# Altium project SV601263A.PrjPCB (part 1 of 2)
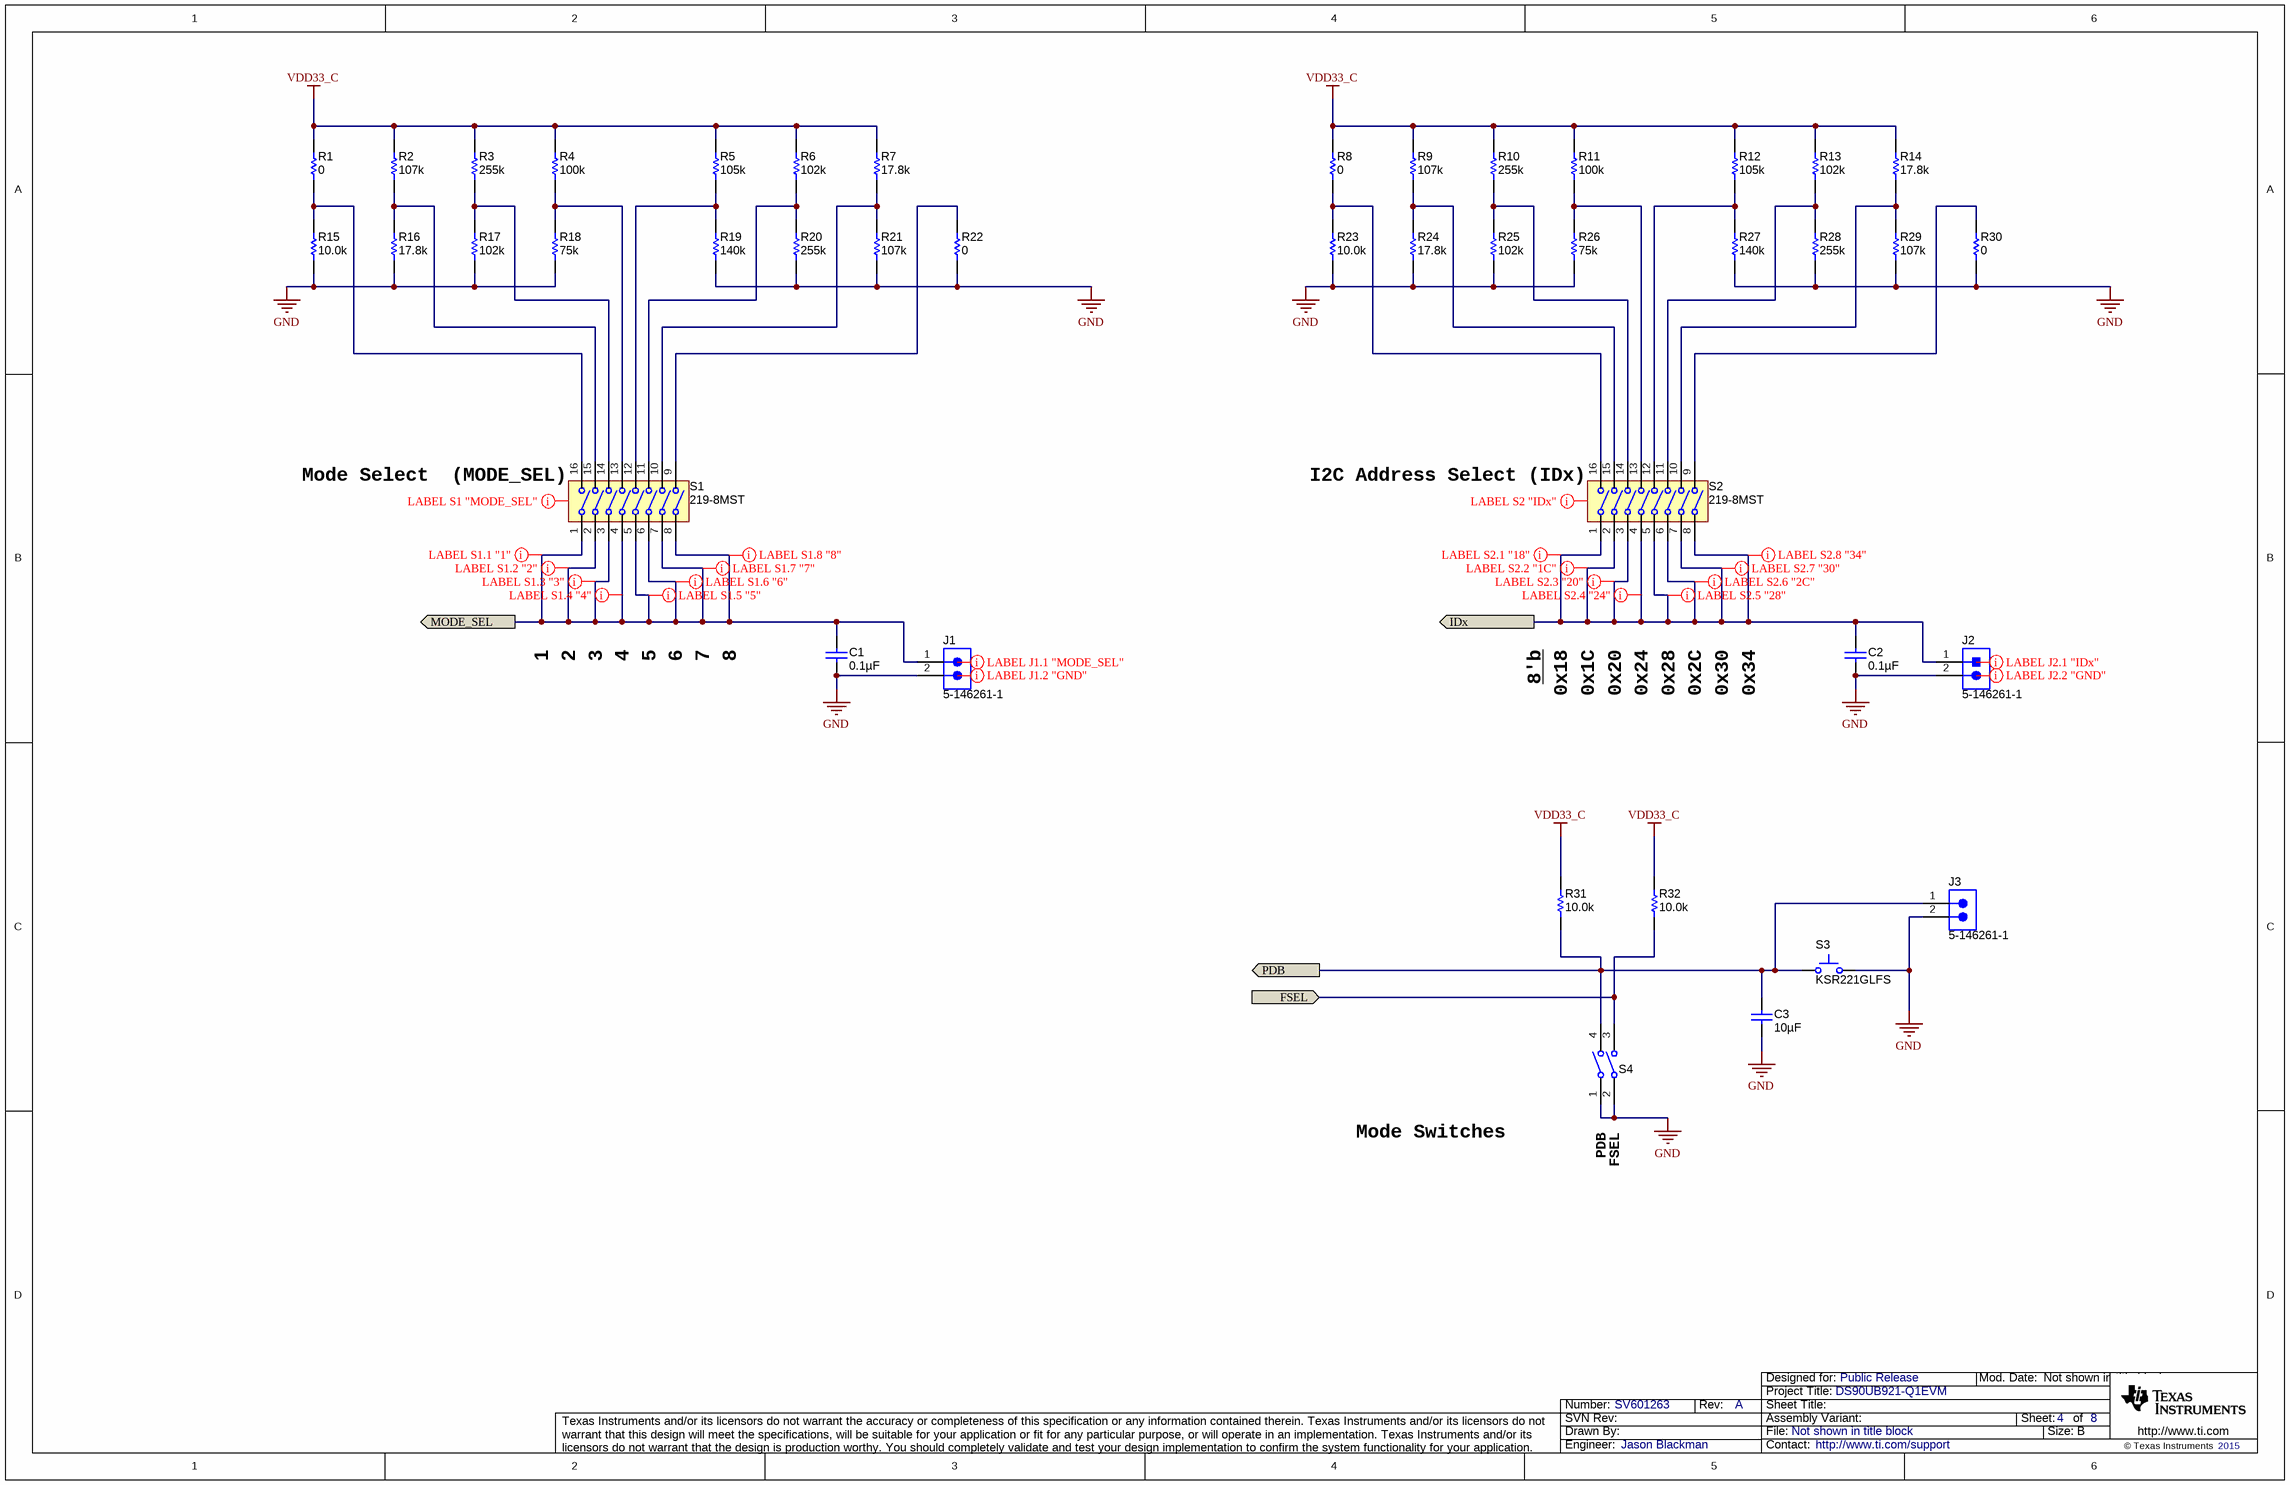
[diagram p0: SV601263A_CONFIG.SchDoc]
CopyrightYear: 2015; PCB_Layout: A; PCB_Rev: A; PRJ_Customer: Public Release; PRJ_Engineer: Jason Blackman; PRJ_Number: SV601263; PRJ_Title: DS90UB921-Q1EVM; SCH_Rev: A; TechSupport: http://www.ti.com/support
7 sheets, 306 parts. Net scope: flat (ports and power ports of the same name join across sheets).
Board file: SV601263A.PcbDoc
Sheets:
  SV601263A_CONFIG.SchDoc
  SV601263A_CONNECTORS.SchDoc
  SV601263A_Cover Sheet_Block.SchDoc
  SV601263A_DS90UB921.SchDoc
  SV601263A_LED.SchDoc
  SV601263A_MSP430F5529.SchDoc
  SV601263A_Power.SchDoc

## Sheet SV601263A_CONFIG.SchDoc
size 431 x 279 mm; Date: Not shown in title block; ApprovedBy: Not shown in title block; CheckedBy: Not shown in title block; Author: Not shown in title block; CompanyName: Not shown in title block; Engineer: Not shown in title block; Organization: Not shown in title block; Address1: Not shown in title block; Address2: Not shown in title block; Address3: Not shown in title block; Address4: Not shown in title block; DocumentNumber: 6; Revision: Use project parameter SCH_Rev; SheetNumber: 4; SheetTotal: 8

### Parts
C1  ValueDisplayed: 0.1µF  [0402]  (hidden comment: GRM155R71C104KA88D)
C2  ValueDisplayed: 0.1µF  [0402]  (hidden comment: GRM155R71C104KA88D)
C3  ValueDisplayed: 10µF  [0805_HV]  (hidden comment: GRM21BR71A106KE51L)
J1  5-146261-1  [CONN_5-146261-1]
J2  5-146261-1  [CONN_5-146261-1]
J3  5-146261-1  [CONN_5-146261-1]
R1  value 0  [0402]  (hidden comment: ERJ-2GE0R00X)
R2  value 107k  [0402]  (hidden comment: CRCW0402107KFKED)
R3  value 255k  [0402]  (hidden comment: CRCW0402255KFKED)
R4  value 100k  [0402]  (hidden comment: ERJ-2RKF1003X)
R5  value 105k  [0402]  (hidden comment: CRCW0402105KFKED)
R6  value 102k  [0402]  (hidden comment: CRCW0402102KFKED)
R7  value 17.8k  [0402]  (hidden comment: CRCW040217K8FKED)
R8  value 0  [0402]  (hidden comment: ERJ-2GE0R00X)
R9  value 107k  [0402]  (hidden comment: CRCW0402107KFKED)
R10  value 255k  [0402]  (hidden comment: CRCW0402255KFKED)
R11  value 100k  [0402]  (hidden comment: ERJ-2RKF1003X)
R12  value 105k  [0402]  (hidden comment: CRCW0402105KFKED)
R13  value 102k  [0402]  (hidden comment: CRCW0402102KFKED)
R14  value 17.8k  [0402]  (hidden comment: CRCW040217K8FKED)
R15  ValueDisplayed: 10.0k  [0402]  (hidden comment: CRCW040210K0FKED)
R16  value 17.8k  [0402]  (hidden comment: CRCW040217K8FKED)
R17  value 102k  [0402]  (hidden comment: CRCW0402102KFKED)
R18  value 75k  [0402]  (hidden comment: CRCW040275K0JNED)
R19  value 140k  [0402]  (hidden comment: CRCW0402140KFKED)
R20  value 255k  [0402]  (hidden comment: CRCW0402255KFKED)
R21  value 107k  [0402]  (hidden comment: CRCW0402107KFKED)
R22  value 0  [0402]  (hidden comment: ERJ-2GE0R00X)
R23  ValueDisplayed: 10.0k  [0402]  (hidden comment: CRCW040210K0FKED)
R24  value 17.8k  [0402]  (hidden comment: CRCW040217K8FKED)
R25  value 102k  [0402]  (hidden comment: CRCW0402102KFKED)
R26  value 75k  [0402]  (hidden comment: CRCW040275K0JNED)
R27  value 140k  [0402]  (hidden comment: CRCW0402140KFKED)
R28  value 255k  [0402]  (hidden comment: CRCW0402255KFKED)
R29  value 107k  [0402]  (hidden comment: CRCW0402107KFKED)
R30  value 0  [0402]  (hidden comment: ERJ-2GE0R00X)
R31  ValueDisplayed: 10.0k  [0402]  (hidden comment: CRCW040210K0FKED)
R32  ValueDisplayed: 10.0k  [0402]  (hidden comment: CRCW040210K0FKED)
S1  219-8MST  [SW_219-8MST]
S2  219-8MST  [SW_219-8MST]
S3  KSR221GLFS  [KSR]
S4  218-2LPST  [SW_218-2LP]  (value not drawn)

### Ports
FSEL, IDx, MODE_SEL, PDB

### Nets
GND: C1.2 C2.2 C3.2 J1.2 J2.2 J3.2 R15.1 R16.1 R17.1 R18.1 R19.1 R20.1 R21.1 R22.1 R23.1 R24.1 R25.1 R26.1 R27.1 R28.1 R29.1 R30.1 S3.2 S4.1 S4.2
VDD33_C: R1.2 R2.2 R3.2 R4.2 R5.2 R6.2 R7.2 R8.2 R9.2 R10.2 R11.2 R12.2 R13.2 R14.2 R31.2 R32.2
FSEL: R32.1 S4.3 ; port FSEL
IDx: C2.1 J2.1 S2.1 S2.2 S2.3 S2.4 S2.5 S2.6 S2.7 S2.8 ; port IDx
MODE_SEL: C1.1 J1.1 S1.1 S1.2 S1.3 S1.4 S1.5 S1.6 S1.7 S1.8 ; port MODE_SEL
NetC3_1: C3.1 J3.1 R31.1 S3.1 S4.4 ; port PDB
NetR1_1: R1.1 R15.2 S1.16(1A)
NetR2_1: R2.1 R16.2 S1.15(2A)
NetR3_1: R3.1 R17.2 S1.14(3A)
NetR4_1: R4.1 R18.2 S1.13(4A)
NetR5_1: R5.1 R19.2 S1.12(5A)
NetR6_1: R6.1 R20.2 S1.11(6A)
NetR7_1: R7.1 R21.2 S1.10(7A)
NetR8_1: R8.1 R23.2 S2.16(1A)
NetR9_1: R9.1 R24.2 S2.15(2A)
NetR10_1: R10.1 R25.2 S2.14(3A)
NetR11_1: R11.1 R26.2 S2.13(4A)
NetR12_1: R12.1 R27.2 S2.12(5A)
NetR13_1: R13.1 R28.2 S2.11(6A)
NetR14_1: R14.1 R29.2 S2.10(7A)
NetR22_2: R22.2 S1.9(8A)
NetR30_2: R30.2 S2.9(8A)

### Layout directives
mark named LABEL S2 "IDx": (no net found under the mark)
rule Undefined: (no net found under the mark), IDx, MODE_SEL
mark named LABEL S1 "MODE_SEL": (no net found under the mark)

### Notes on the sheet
- (near S1) Mode Select  (MODE_SEL)
- (near S2) I2C Address Select (IDx)
- 1
- 2
- 3
- 4
- 5
- 6
- 7
- 8
- 8'b
- 0x18
- 0x1C
- 0x20
- 0x24
- 0x28
- 0x2C
- 0x30
- 0x34
- Mode Switches
- PDB
- FSEL

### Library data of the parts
C1 C2 = GRM155R71C104KA88D: CAP, CERM, 0.1uF, 16V, +/-10%, X7R, 0402; Manufacturer: MuRata; Polarized: N; CompType: Capacitor; U/M: EA; Cap_F: 0.0000001; Tolerance_%: 10; Value1: Unknown; VDC_V: 16; TaMin_C: -55; TaMax_C: 125
C3 = GRM21BR71A106KE51L: CAP, CERM, 10uF, 10V, +/-10%, X7R, 0805; Manufacturer: MuRata; Polarized: N; CompType: Capacitor; U/M: EA; Cap_F: 0.00001; Tolerance_%: 10; ESR_Ohm: 0.003; Value1: 0.003 ohm; TaMin_C: -55; TaMax_C: 125; Cap_Case: 0805
J1-J3 = 5-146261-1: Header, 100mil, 2x1, Gold, TH; Manufacturer: TE Connectivity; SymbolCreator: a0412235; U/M: EA
R1 R8 R22 R30 = ERJ-2GE0R00X: RES, 0 ohm, 5%, 0.063W, 0402; Manufacturer: Panasonic; CompType: Resistor; Value_Code: 0000; Tolerance_%: 5; Power_W: 0.063; VDC_V: 50; TempCo: 600 ppm/C; EIA_Code: E24; U/M: EA
R2 R9 R21 R29 = CRCW0402107KFKED: RES, 107k ohm, 1%, 0.063W, 0402; Manufacturer: Vishay-Dale; CompType: Resistor; Res_ohm: 107000; Tolerance_%: 1; Power_W: 0.063; VDC_V: 50; TempCo: 100 ppm/C; EIA_Code: E96; U/M: EA
R3 R10 R20 R28 = CRCW0402255KFKED: RES, 255k ohm, 1%, 0.063W, 0402; Manufacturer: Vishay-Dale; CompType: Resistor; Res_ohm: 255000; Tolerance_%: 1; Power_W: 0.063; VDC_V: 50; TempCo: 100 ppm/C; EIA_Code: E96; U/M: EA
R4 R11 = ERJ-2RKF1003X: RES, 100k ohm, 1%, 0.1W, 0402; Manufacturer: Panasonic; CompType: Resistor; Res_ohm: 100000; Tolerance_%: 1; Power_W: 0.1; VDC_V: 50; TempCo: 100 ppm/C; EIA_Code: E96; U/M: EA
R5 R12 = CRCW0402105KFKED: RES, 105k ohm, 1%, 0.063W, 0402; Manufacturer: Vishay-Dale; CompType: Resistor; Res_ohm: 105000; Tolerance_%: 1; Power_W: 0.063; VDC_V: 50; TempCo: 100 ppm/C; EIA_Code: E96; U/M: EA
R6 R13 R17 R25 = CRCW0402102KFKED: RES, 102k ohm, 1%, 0.063W, 0402; Manufacturer: Vishay-Dale; CompType: Resistor; Res_ohm: 102000; Tolerance_%: 1; Power_W: 0.063; VDC_V: 50; TempCo: 100 ppm/C; EIA_Code: E96; U/M: EA
R7 R14 R16 R24 = CRCW040217K8FKED: RES, 17.8k ohm, 1%, 0.063W, 0402; Manufacturer: Vishay-Dale; CompType: Resistor; Res_ohm: 17800; Value_Code: 17k8; Tolerance_%: 1; Power_W: 0.063; VDC_V: 50; TempCo: 100 ppm/C; EIA_Code: E96; U/M: EA
R15 R23 R31 R32 = CRCW040210K0FKED: RES, 10.0 k, 1%, 0.063 W, 0402; Manufacturer: Vishay-Dale; CompType: Resistor; Value: 10.0k; Res_ohm: 10000; Value_Code: 10k0; Tolerance_%: 1; Power_W: 0.063; Value2: 0.063W; VDC_V: 50; TempCo: 100 ppm/C; EIA_Code: E96; U/M: EA
R18 R26 = CRCW040275K0JNED: RES, 75k ohm, 5%, 0.063W, 0402; Manufacturer: Vishay-Dale; CompType: Resistor; Res_ohm: 75000; Value_Code: 75k0; Tolerance_%: 5; Power_W: 0.063; VDC_V: 50; TempCo: 200 ppm/C; EIA_Code: E24; U/M: EA
R19 R27 = CRCW0402140KFKED: RES, 140k ohm, 1%, 0.063W, 0402; Manufacturer: Vishay-Dale; CompType: Resistor; Res_ohm: 140000; Tolerance_%: 1; Power_W: 0.063; VDC_V: 50; TempCo: 100 ppm/C; EIA_Code: E96; U/M: EA
S1 S2 = 219-8MST: Switch, Slide, SPST 8 poles, SMT; Manufacturer: CTS Electrocomponents; SymbolCreator: a0412235; VDC_V: 20; SwitchFunction: Off-On; PositionCount: 8; CurrentRating_mA: 100
S3 = KSR221GLFS: Switch, Normally open, 2.3N force, 200k operations, SMD; Manufacturer: C and K Components; Circuit: SPST Switch; VDC_V: 32; SwitchFunction: Off-Mom; PositionCount: 1; CurrentRating_mA: 1001
S4 = 218-2LPST: Switch, SPST, 2 Pos, 25mA, 24VDC, SMD; Manufacturer: CTS Electrocomponents; SymbolCreator: Altium; VDC_V: 24; SwitchFunction: Off-On; PositionCount: 2; CurrentRating_mA: 25

## Sheet SV601263A_CONNECTORS.SchDoc
size 431 x 279 mm; Date: Not shown in title block; ApprovedBy: Not shown in title block; CheckedBy: Not shown in title block; Author: Not shown in title block; CompanyName: Not shown in title block; Engineer: Not shown in title block; Organization: Not shown in title block; Address1: Not shown in title block; Address2: Not shown in title block; Address3: Not shown in title block; Address4: Not shown in title block; DocumentNumber: 7; Revision: Use project parameter SCH_Rev; SheetNumber: 5; SheetTotal: 8
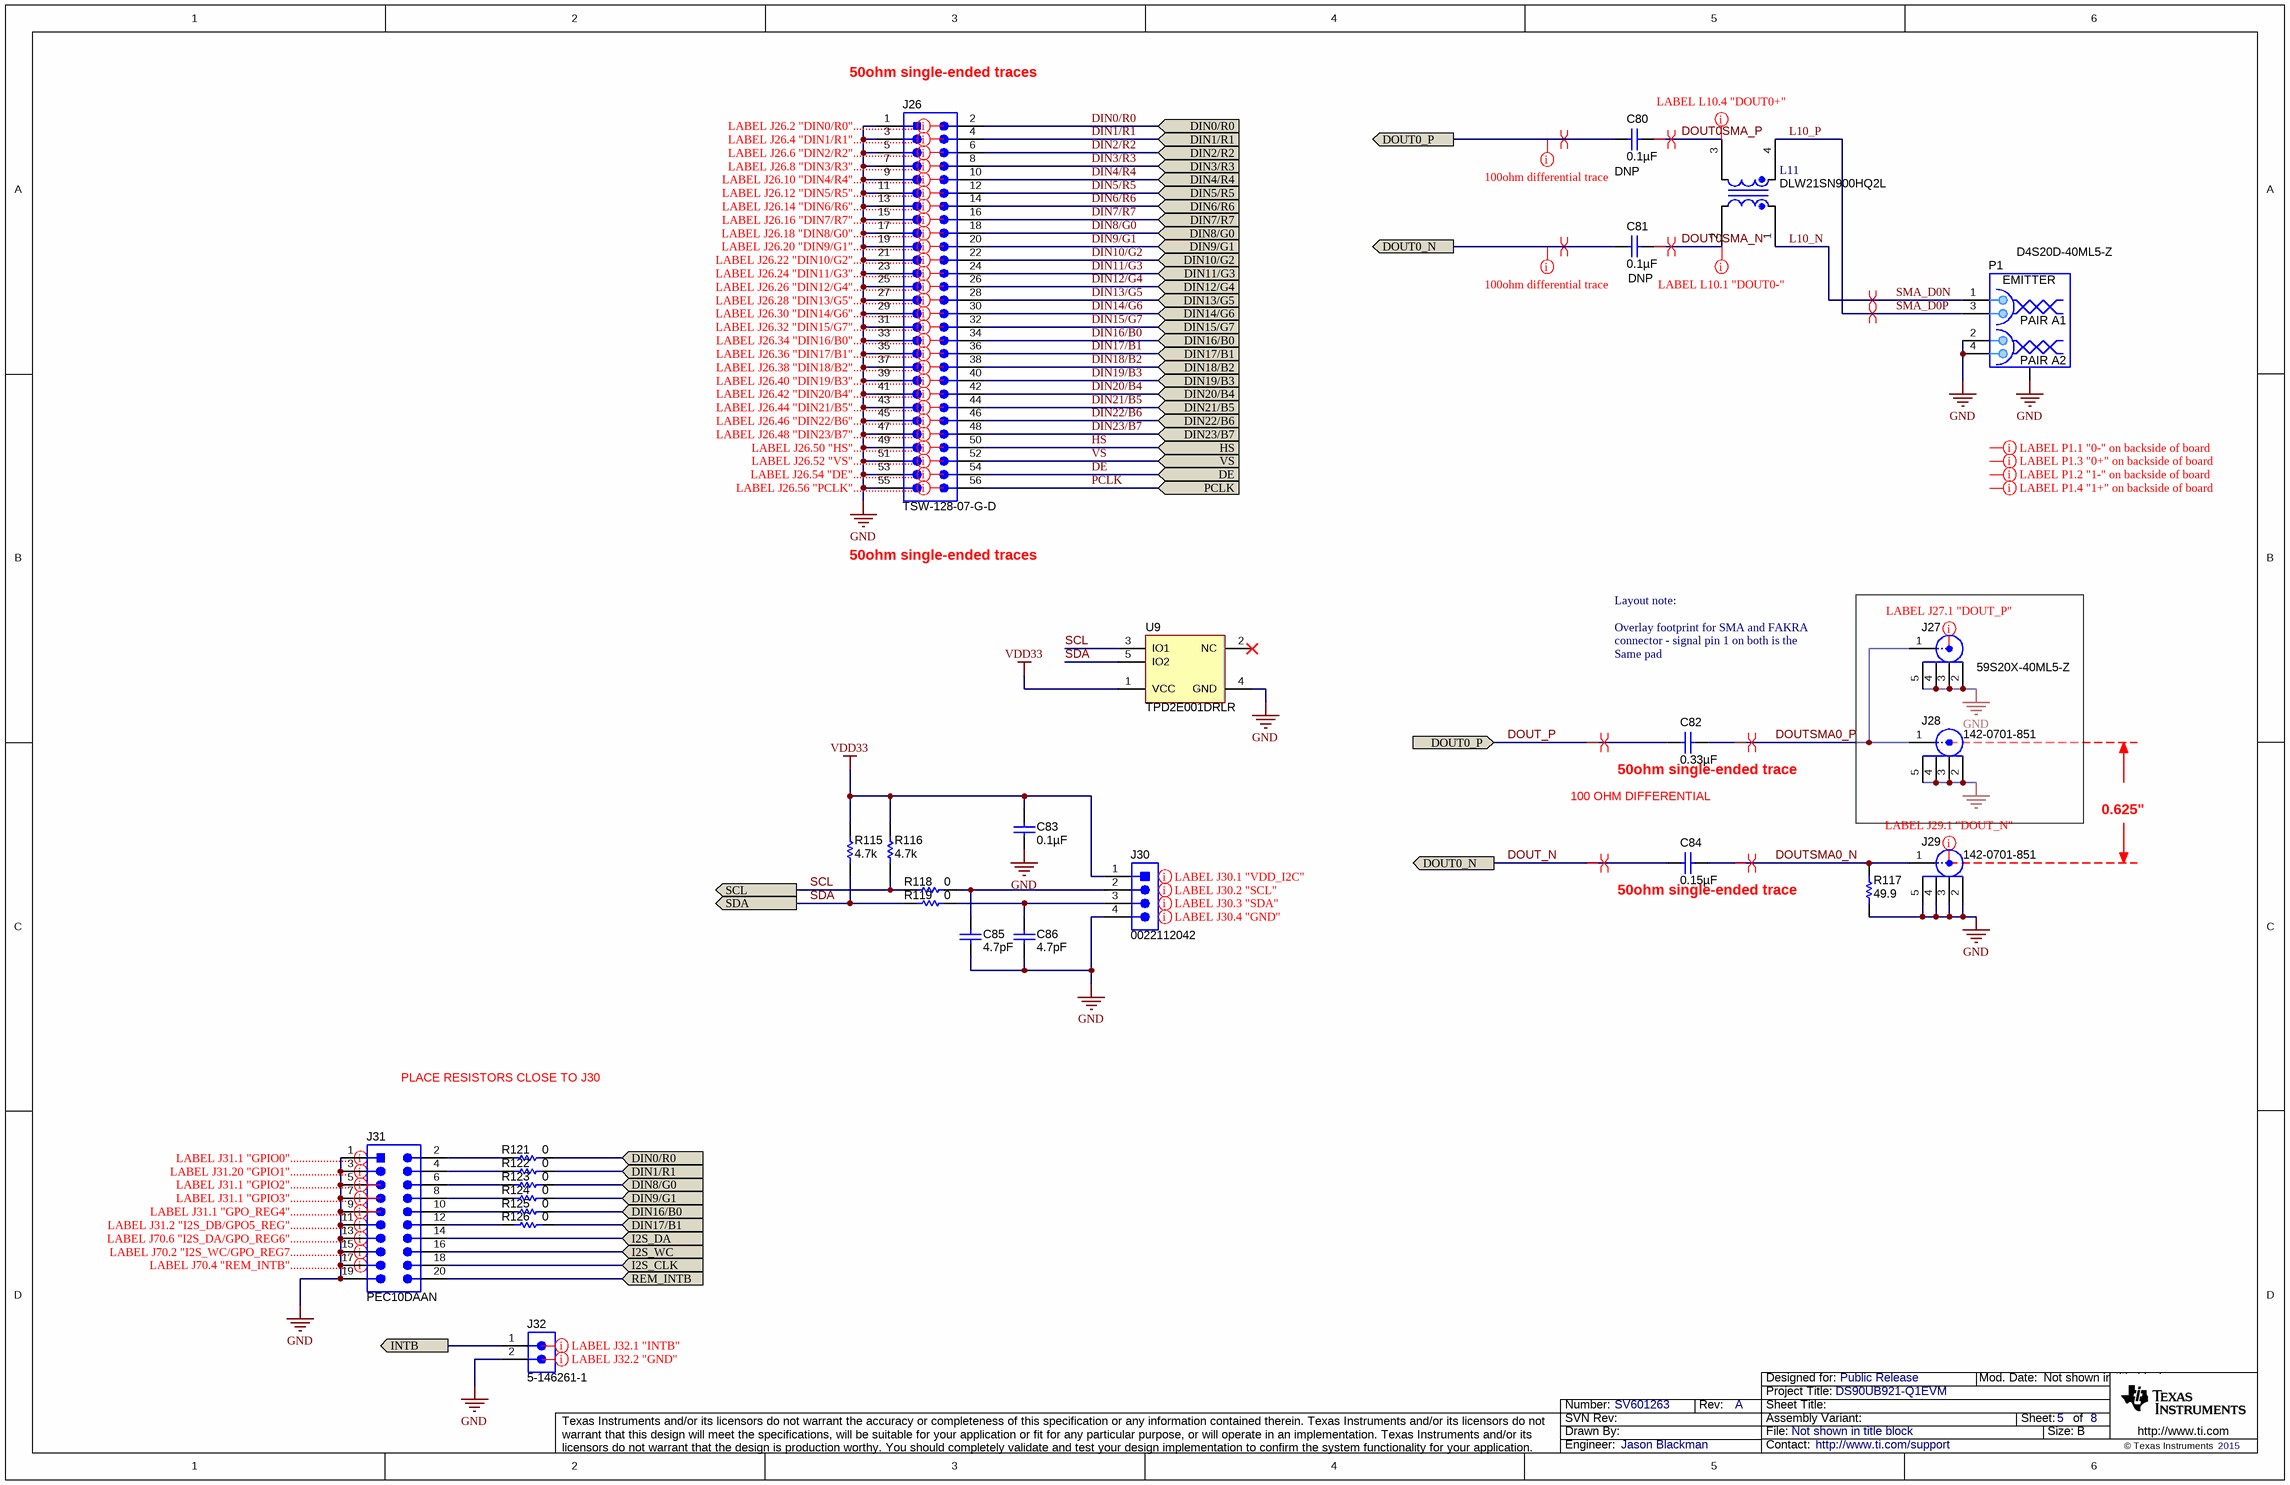
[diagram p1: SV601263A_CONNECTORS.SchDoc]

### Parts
C80  DNP  ValueDisplayed: 0.1µF  [0402]
C81  DNP  ValueDisplayed: 0.1µF  [0402]
C82  ValueDisplayed: 0.33µF  [0402]  (hidden comment: C1005X5R1A334K050BB)
C83  ValueDisplayed: 0.1µF  [0402]  (hidden comment: GRM155R71C104KA88D)
C84  ValueDisplayed: 0.15µF  [0402]  (hidden comment: C1005X5R1A154K050BC)
C85  ValueDisplayed: 4.7pF  [0402]  (hidden comment: GRM1555C1E4R7CA01D)
C86  ValueDisplayed: 4.7pF  [0402]  (hidden comment: GRM1555C1E4R7CA01D)
J26  TSW-128-07-G-D  [Samtec_TSW-128-07-G-D]
J27  59S20X-40ML5-Z  [Rosenberger_59S20X-40ML5-Z]
J28  142-0701-851  [Emerson_142-0701-851]
J29  142-0701-851  [Emerson_142-0701-851]
J30  0022112042  [CONN_22112042]
J31  PEC10DAAN  [SULLINS_PEC10DAAN]
J32  5-146261-1  [CONN_5-146261-1]
L11  DLW21SN900HQ2L  [IND_DLW21S]
P1  D4S20D-40ML5-Z  [Rosenberger_D4S20L-40MA5_NoTopLayerPads]
R115  value 4.7k  [0402]  (hidden comment: CRCW04024K70JNED)
R116  value 4.7k  [0402]  (hidden comment: CRCW04024K70JNED)
R117  value 49.9  [0402]  (hidden comment: CRCW040249R9FKED)
R118  value 0  [0402]  (hidden comment: ERJ-2GE0R00X)
R119  value 0  [0402]  (hidden comment: ERJ-2GE0R00X)
R121  ValueDisplayed: 0  [0201M]  (hidden comment: ERJ-1GE0R00C)
R122  ValueDisplayed: 0  [0201M]  (hidden comment: ERJ-1GE0R00C)
R123  ValueDisplayed: 0  [0201M]  (hidden comment: ERJ-1GE0R00C)
R124  ValueDisplayed: 0  [0201M]  (hidden comment: ERJ-1GE0R00C)
R125  ValueDisplayed: 0  [0201M]  (hidden comment: ERJ-1GE0R00C)
R126  ValueDisplayed: 0  [0201M]  (hidden comment: ERJ-1GE0R00C)
U9  TPD2E001DRLR  [DRL0005A]

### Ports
DE, DIN0/R0, DIN1/R1, DIN2/R2, DIN3/R3, DIN4/R4, DIN5/R5, DIN6/R6, DIN7/R7, DIN8/G0, DIN9/G1, DIN10/G2, DIN11/G3, DIN12/G4, DIN13/G5, DIN14/G6, DIN15/G7, DIN16/B0, DIN17/B1, DIN18/B2, DIN19/B3, DIN20/B4, DIN21/B5, DIN22/B6, DIN23/B7, DOUT0_N, DOUT0_P, HS, I2S_CLK, I2S_DA, I2S_WC, INTB, PCLK, REM_INTB, SCL, SDA, VS

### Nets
GND: C83.1 C85.2 C86.2 J26.1 J26.3 J26.5 J26.7 J26.9 J26.11 J26.13 J26.15 J26.17 J26.19 J26.21 J26.23 J26.25 J26.27 J26.29 J26.31 J26.33 J26.35 J26.37 J26.39 J26.41 J26.43 J26.45 J26.47 J26.49 J26.51 J26.53 J26.55 J27.2 J27.3 J27.4 J27.5 J28.2 J28.3 J28.4 J28.5 J29.2 J29.3 J29.4 J29.5 J30.4 J31.1 J31.3 J31.5 J31.7 J31.9 J31.11 J31.13 J31.15 J31.17 J31.19 J32.2 P1.2 P1.4 P1.MH R117.1 U9.4(GND)
VDD33: C83.2 J30.1 R115.2 R116.2 U9.1(VCC)
DE: J26.54 ; port DE
DIN0/R0: J26.2 R121.2 ; port DIN0/R0
DIN1/R1: J26.4 R122.2 ; port DIN1/R1
DIN2/R2: J26.6 ; port DIN2/R2
DIN3/R3: J26.8 ; port DIN3/R3
DIN4/R4: J26.10 ; port DIN4/R4
DIN5/R5: J26.12 ; port DIN5/R5
DIN6/R6: J26.14 ; port DIN6/R6
DIN7/R7: J26.16 ; port DIN7/R7
DIN8/G0: J26.18 R123.2 ; port DIN8/G0
DIN9/G1: J26.20 R124.2 ; port DIN9/G1
DIN10/G2: J26.22 ; port DIN10/G2
DIN11/G3: J26.24 ; port DIN11/G3
DIN12/G4: J26.26 ; port DIN12/G4
DIN13/G5: J26.28 ; port DIN13/G5
DIN14/G6: J26.30 ; port DIN14/G6
DIN15/G7: J26.32 ; port DIN15/G7
DIN16/B0: J26.34 R125.2 ; port DIN16/B0
DIN17/B1: J26.36 R126.2 ; port DIN17/B1
DIN18/B2: J26.38 ; port DIN18/B2
DIN19/B3: J26.40 ; port DIN19/B3
DIN20/B4: J26.42 ; port DIN20/B4
DIN21/B5: J26.44 ; port DIN21/B5
DIN22/B6: J26.46 ; port DIN22/B6
DIN23/B7: J26.48 ; port DIN23/B7
DOUT0SMA_N: C81.1 L11.2
DOUT0SMA_P: C80.1 L11.3
DOUT_N: C81.2 C84.2 ; port DOUT0_N
DOUT_P: C80.2 C82.2 ; port DOUT0_P
DOUTSMA0_N: C84.1 J29.1 R117.2
DOUTSMA0_P: C82.1 J27.1 J28.1
HS: J26.50 ; port HS
I2S_CLK: J31.18 ; port I2S_CLK
I2S_DA: J31.14 ; port I2S_DA
I2S_WC: J31.16 ; port I2S_WC
L10_N: L11.1 P1.1  [also labelled SMA_D0N]
L10_P: L11.4 P1.3  [also labelled SMA_D0P]
PCLK: J26.56 ; port PCLK
REM_INTB: J31.20 ; port REM_INTB
SCL: R116.1 R118.1 U9.3(IO1) ; port SCL
SDA: R115.1 R119.1 U9.5(IO2) ; port SDA
VS: J26.52 ; port VS
NetC85_1: C85.1 J30.2 R118.2
NetC86_1: C86.1 J30.3 R119.2
NetJ31_2: J31.2 R121.1
NetJ31_4: J31.4 R122.1
NetJ31_6: J31.6 R123.1
NetJ31_8: J31.8 R124.1
NetJ31_10: J31.10 R125.1
NetJ31_12: J31.12 R126.1
NetJ32_1: J32.1 ; port INTB

Not connected (* = marked no-connect by the designer): U9 2(NC)*

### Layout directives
differential pair: DOUT0SMA_N, DOUT0SMA_P, DOUT_N, DOUT_P, DOUTSMA0_N, DOUTSMA0_P, L10_N, L10_P
rule Undefined: (no net found under the mark), DOUT0SMA_N, DOUT0SMA_P, DOUT_N, DOUT_P

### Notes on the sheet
- (near J26) 50ohm single-ended traces
- 50ohm single-ended traces
- Layout note:
- Overlay footprint for SMA and FAKRA
- connector - signal pin 1 on both is the
- Same pad
- (near C82) 50ohm single-ended trace
- 100 OHM DIFFERENTIAL
- 0.625"
- (near C84) 50ohm single-ended trace
- PLACE RESISTORS CLOSE TO J30

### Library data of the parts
C80 C81 = GCM155R71H104KE02D: CAP, CERM, 0.1 µF, 50 V, +/- 10%, X7R, AEC-Q200 Grade 1, 0402; Manufacturer: MuRata; Polarized: N; CompType: Capacitor; Value: 0.1uF; U/M: EA; Cap_F: 0.0000001; Tolerance_%: 10; Value1: Unknown; VDC_V: 50; Value2: 50V; TaMin_C: -55; TaMax_C: 125; AEC Category: Q200; AEC Qualified: Y; AEC Grade: 1
C82 = C1005X5R1A334K050BB: CAP, CERM, 0.33 µF, 10 V, +/- 10%, X5R, 0402; Manufacturer: TDK; Polarized: N; CompType: Capacitor; Value: 0.33uF; U/M: EA; Cap_F: 0.00000033; Tolerance_%: 10; Value1: Unknown; Value2: 10V; TaMin_C: -55; TaMax_C: 85; AEC Category: Q200
C83 = GRM155R71C104KA88D: as C1 on sheet SV601263A_CONFIG
C84 = C1005X5R1A154K050BC: CAP, CERM, 0.15 µF, 10 V, +/- 10%, X5R, 0402; Manufacturer: TDK; Polarized: N; CompType: Capacitor; Value: 0.15uF; U/M: EA; Cap_F: 0.00000015; Tolerance_%: 10; Value1: Unknown; Value2: 10V; TaMin_C: -55; TaMax_C: 85; AEC Category: Q200
C85 C86 = GRM1555C1E4R7CA01D: CAP, CERM, 4.7pF, 25V, +/-5%, C0G/NP0, 0402; Manufacturer: MuRata; Polarized: N; CompType: Capacitor; U/M: EA; Cap_F: 0.0000000000047; Tolerance_%: 5; Value1: Unknown; VDC_V: 25; TaMin_C: -55; TaMax_C: 125
J26 = TSW-128-07-G-D: Header, 100mil, 28x2, Gold, TH; Manufacturer: Samtec; SymbolCreator: Altium; U/M: EA
J27 = 59S20X-40ML5-Z: Connector, RF, 50 Ohm, R/A, TH; Manufacturer: Rosenberger; SymbolCreator: X0208326; U/M: EA
J28 J29 = 142-0701-851: Connector, End launch SMA, 50 ohm, SMT; Manufacturer: Emerson Network Power; SymbolCreator: X0208326; U/M: EA
J30 = 0022112042: Header (friction lock), 100mil, 4x1, Gold, TH; Manufacturer: Molex; SymbolCreator: a0412235; U/M: EA
J31 = PEC10DAAN: Header, 100mil, 10x2, TH; Manufacturer: Sullins Connector Solutions; SymbolCreator: a0412235; U/M: EA
J32 = 5-146261-1: as J1 on sheet SV601263A_CONFIG
L11 = DLW21SN900HQ2L: Coupled inductor, 0.28 A, 0.41 ohm, +/- 25%, SMD; Manufacturer: MuRata; SymbolCreator: a0412235; DCR_ohm: 0.41; Isat: 0.28; Tolerance_%: 25
P1 = D4S20D-40ML5-Z: HSD Right Angle Plug for PCB, TH; Manufacturer: Rosenberger; SymbolCreator: Altium/a0412235; U/M: EA
R115 R116 = CRCW04024K70JNED: RES, 4.7k ohm, 5%, 0.063W, 0402; Manufacturer: Vishay-Dale; CompType: Resistor; Res_ohm: 4700; Value_Code: 4k70; Tolerance_%: 5; Power_W: 0.063; VDC_V: 50; TempCo: 200 ppm/C; EIA_Code: E24; U/M: EA
R117 = CRCW040249R9FKED: RES, 49.9 ohm, 1%, 0.063W, 0402; Manufacturer: Vishay-Dale; CompType: Resistor; Value_Code: 49R9; Tolerance_%: 1; Power_W: 0.063; VDC_V: 50; TempCo: 100 ppm/C; EIA_Code: E96; U/M: EA; BOM_IGNORE: DNL
R118 R119 = ERJ-2GE0R00X: as R1 on sheet SV601263A_CONFIG
R121-R126 = ERJ-1GE0R00C: RES, 0, 5%, 0.05 W, 0201; Manufacturer: Panasonic; CompType: Resistor; Value: 0; Value_Code: 0000; Tolerance_%: 5; Power_W: 0.05; Value2: 0.05W; VDC_V: 15; TempCo: 600 ppm/C; EIA_Code: E24; U/M: EA; AEC Category: Q200
U9 = TPD2E001DRLR: Low-Capacitance + / - 15 kV ESD-Protection Array for High-Speed Data Interfaces, 2 Channels, -40 to +85 degC, 5-pin SOT (DRL), Green (RoHS & no Sb/Br); Manufacturer: Texas Instruments; Alternate Manufacturer: None; Alternate PartNumber: Equivalent; Breakdown Voltage(Min)(V): 11; IEC 61000-4-2 Air-Gap(+/- kV): 15; IEC 61000-4-2 Contact(+/- kV): 8; IO Capacitance(Typ)(pF): 1.5; IO Leakage Current(nA): 1; SubFamily: ESD Solution; USB High Speed: TRUE

## Sheet SV601263A_Cover Sheet_Block.SchDoc: Block Diagram
size 431 x 279 mm; Date: Not shown in title block; ApprovedBy: Not shown in title block; CheckedBy: Not shown in title block; Author: Not shown in title block; CompanyName: Not shown in title block; Engineer: Jason Blackman; Organization: Not shown in title block; Address1: Not shown in title block; Address2: Not shown in title block; Address3: Not shown in title block; Address4: Not shown in title block; DocumentNumber: 2; Revision: Use project parameter SCH_Rev; SheetNumber: 1; SheetTotal: 8; PageSetup: Record=PageOptions¦CenterHorizontal=True¦CenterVertical=True¦PrintScale=0.95¦XCorrection=1.00¦YCorrection=1.00¦PrintKind=0¦BorderSize=5000000¦LeftOffset=0¦BottomOffset=0¦Orientation=2¦PaperLength=1000¦PaperWidth=1000¦Scale=100¦PaperSource=7¦PrintQuality=600¦MediaType=1¦DitherType=10¦PaperKind=11x17¦PrintScaleMode=1
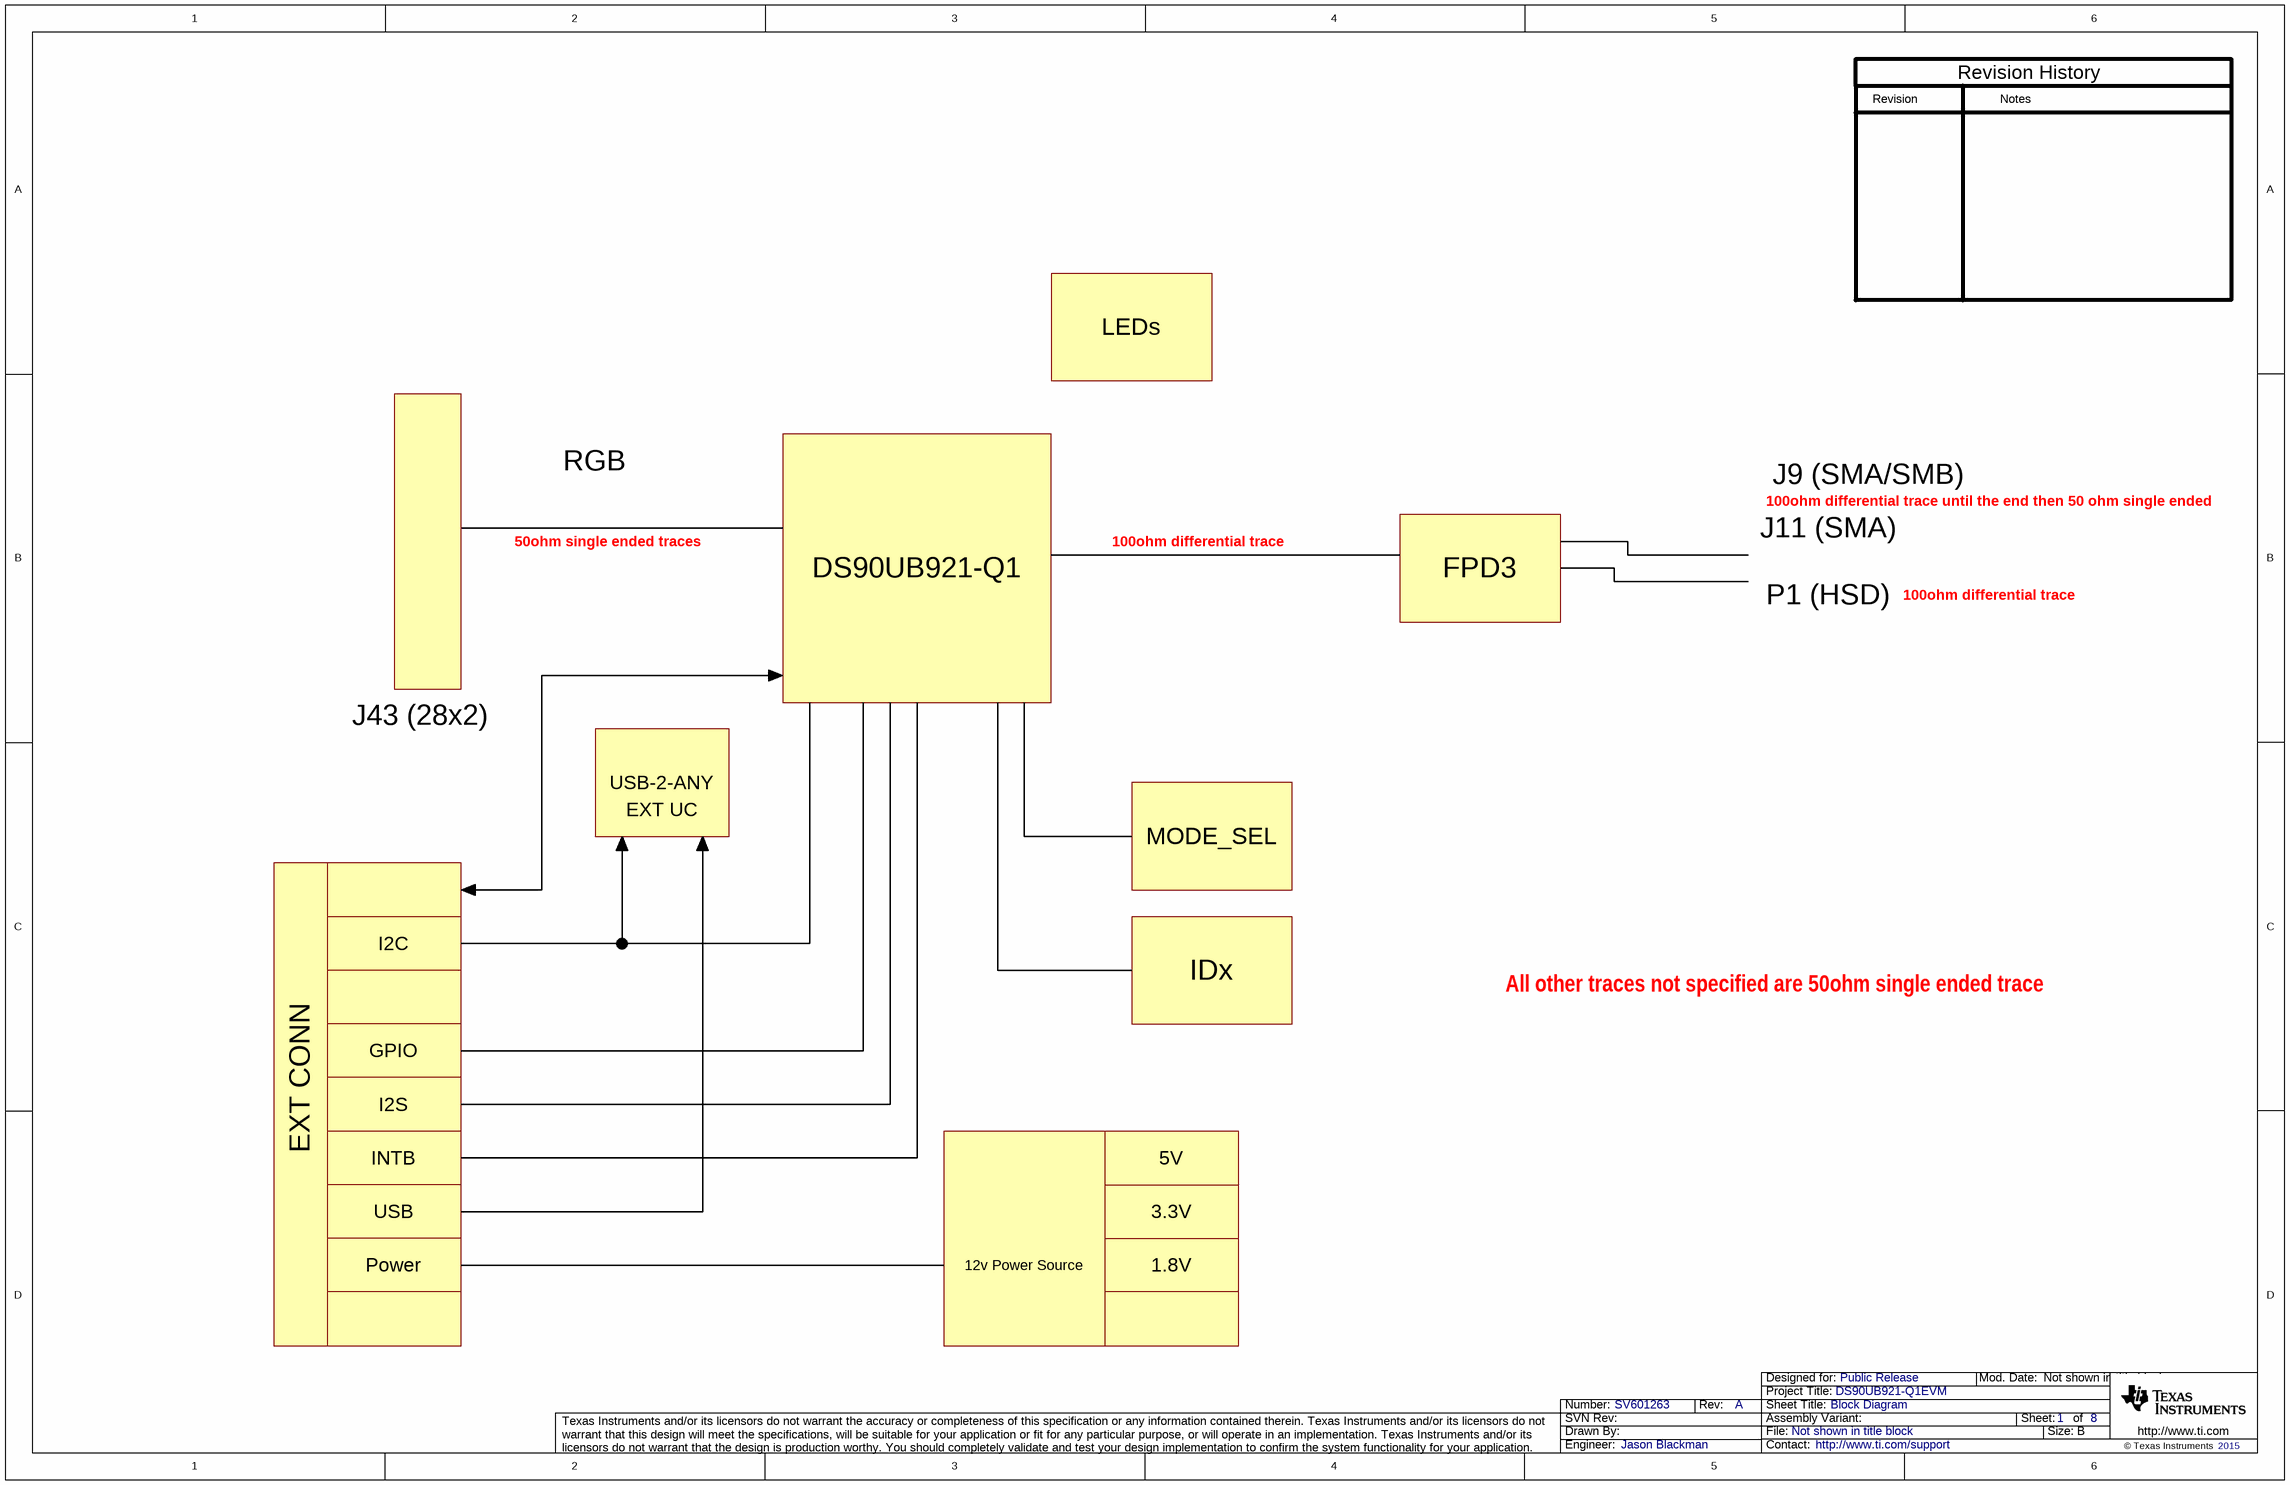
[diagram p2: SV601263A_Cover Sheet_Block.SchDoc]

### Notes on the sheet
- Revision
- Notes
- Revision History
- LEDs
- RGB
- J9 (SMA/SMB)
- 100ohm differential trace until the end then 50 ohm single ended
- 50ohm single ended traces
- DS90UB921-Q1
- 100ohm differential trace
- FPD3
- J11 (SMA)
- P1 (HSD)
- J43 (28x2)
- USB-2-ANY
- EXT UC
- MODE_SEL
- I2C
- IDx
- All other traces not specified are 50ohm single ended trace
- EXT CONN
- GPIO
- I2S
- INTB
- 5V
- USB
- 3.3V
- Power
- 12v Power Source
- 1.8V

## Sheet SV601263A_DS90UB921.SchDoc
size 431 x 279 mm; Date: Not shown in title block; ApprovedBy: Not shown in title block; CheckedBy: Not shown in title block; Author: Not shown in title block; CompanyName: Not shown in title block; Organization: Not shown in title block; Address1: Not shown in title block; Address2: Not shown in title block; Address3: Not shown in title block; Address4: Not shown in title block; DocumentNumber: 4; Revision: Use project parameter SCH_Rev; SheetNumber: 3; SheetTotal: 8; PageSetup: Record=PageOptions¦CenterHorizontal=True¦CenterVertical=True¦PrintScale=0.96¦XCorrection=1.00¦YCorrection=1.00¦PrintKind=0¦BorderSize=5000000¦LeftOffset=0¦BottomOffset=0¦Orientation=2¦PaperLength=1000¦PaperWidth=1000¦Scale=100¦PaperSource=15¦PrintQuality=600¦MediaType=1¦DitherType=10¦PaperKind=11x17¦PrintScaleMode=1
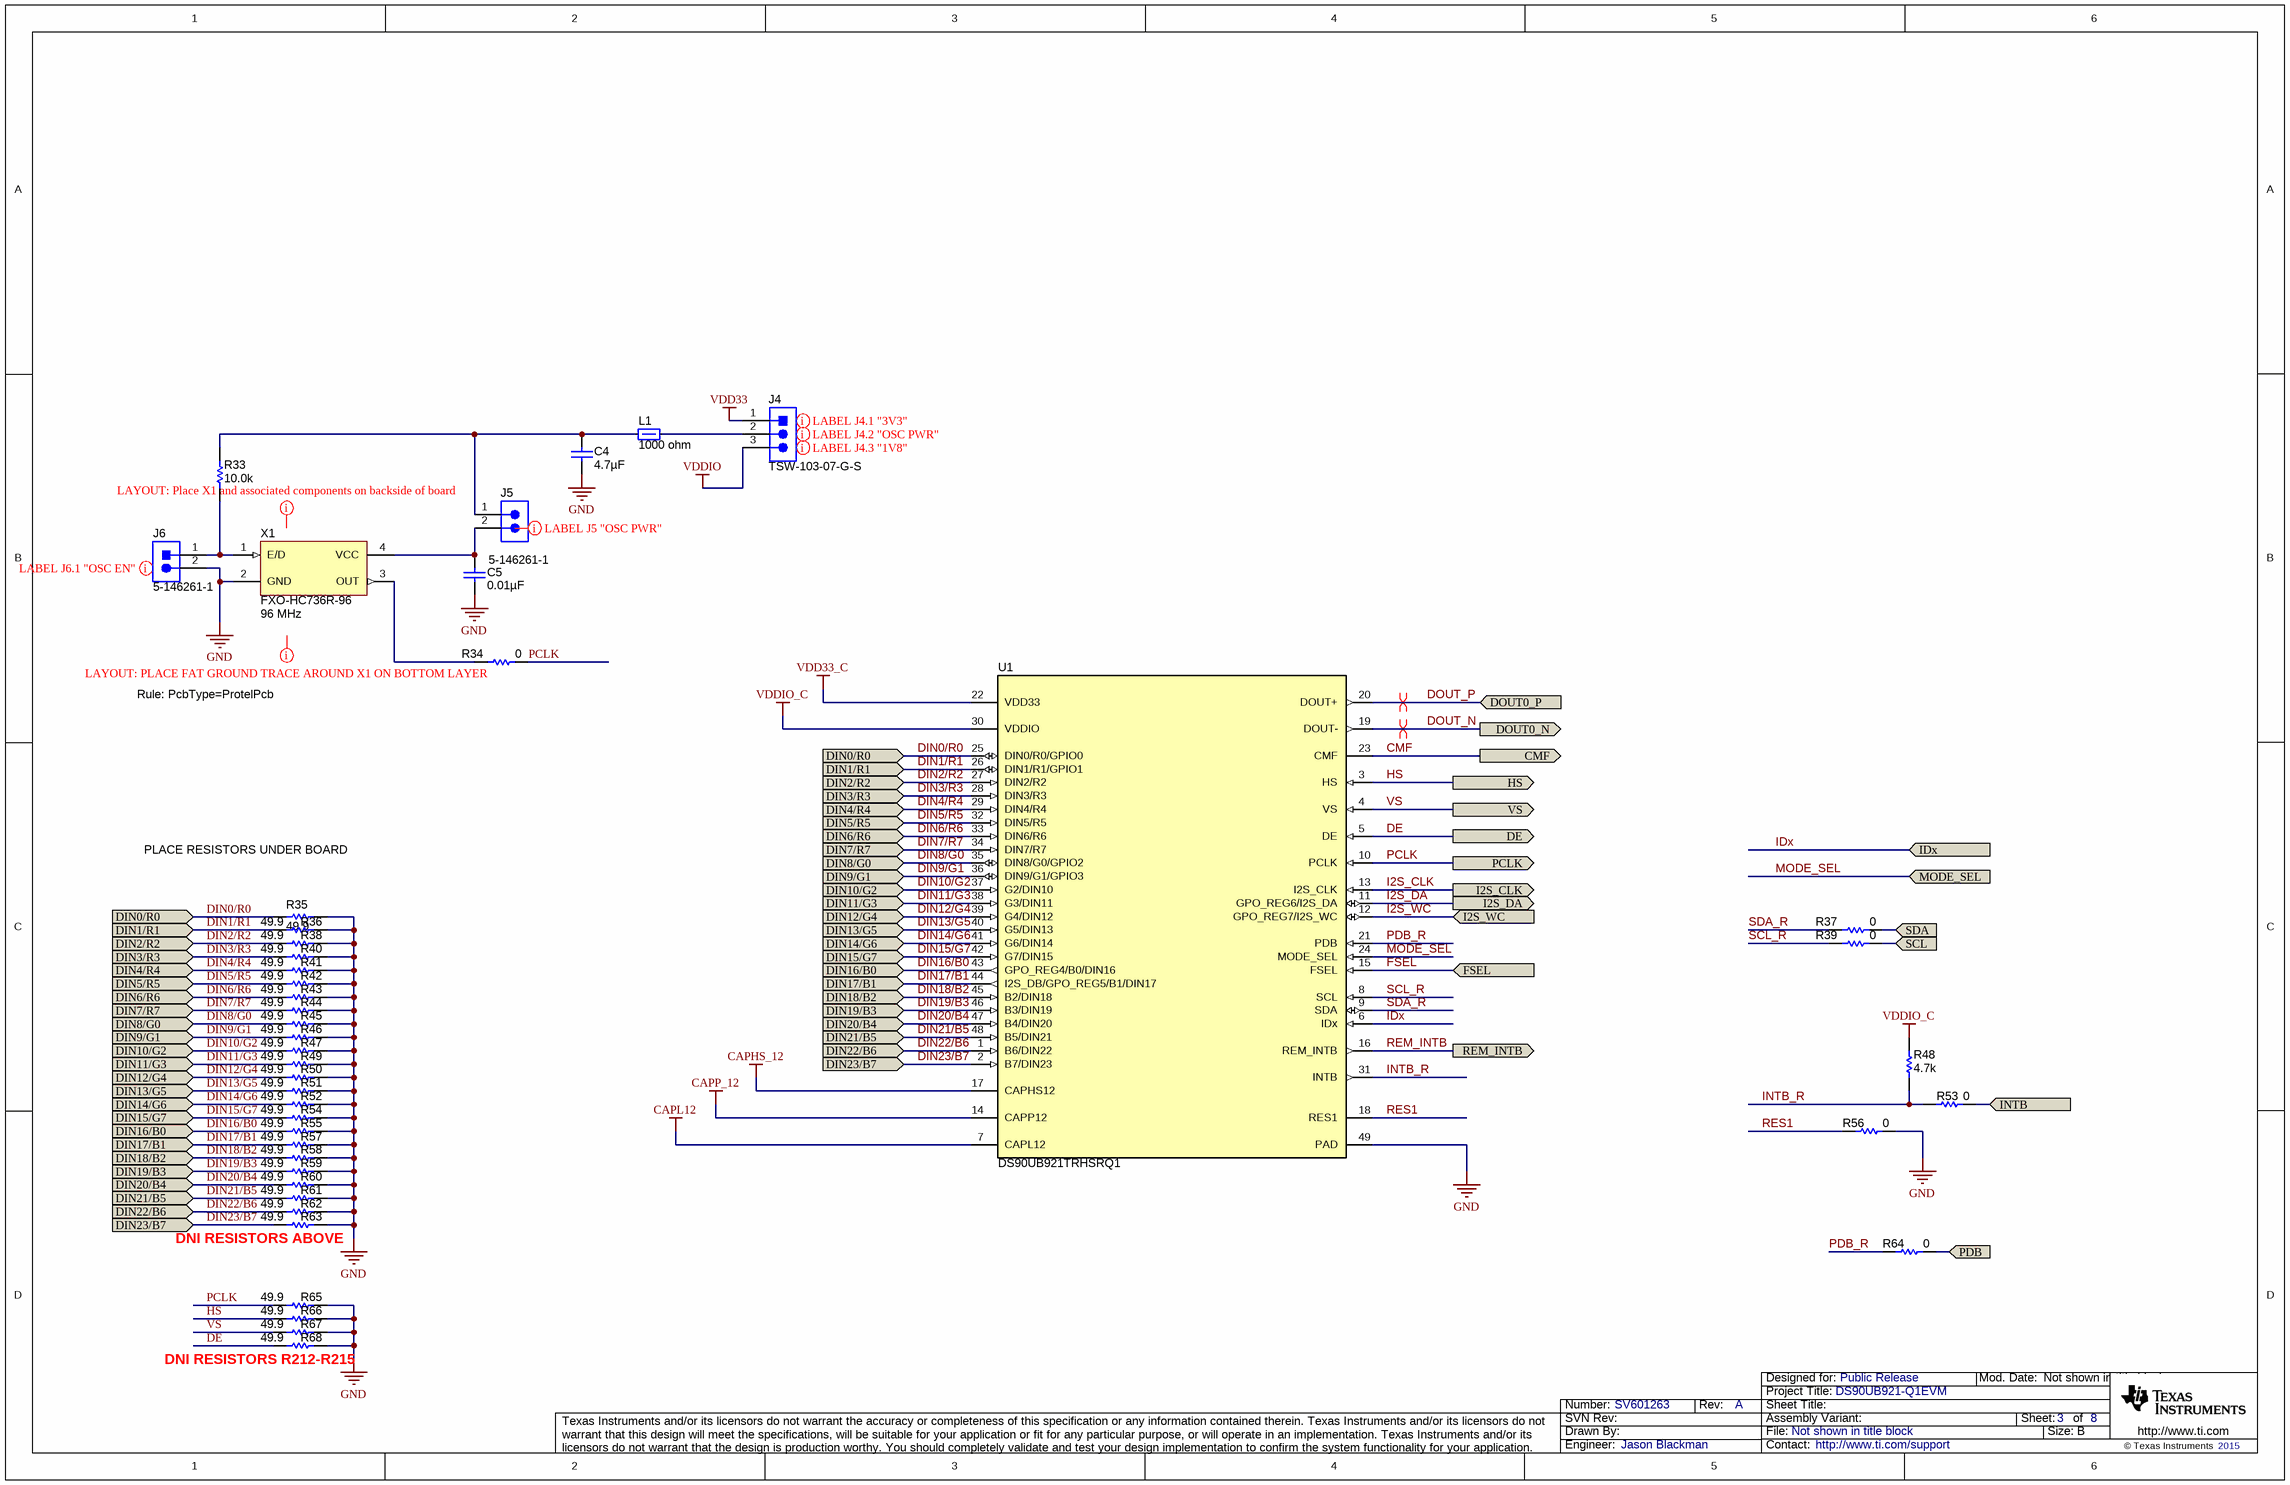
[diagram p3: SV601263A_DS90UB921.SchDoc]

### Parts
C4  ValueDisplayed: 4.7µF  [0805_HV]  (hidden comment: GRM21BR71C475KA73L)
C5  ValueDisplayed: 0.01µF  [0603]  (hidden comment: 06031C103JAT2A)
J4  TSW-103-07-G-S  [TSW-103-07-G-S]
J5  5-146261-1  [CONN_5-146261-1]
J6  5-146261-1  [CONN_5-146261-1]
L1  value 1000 ohm  [0402]  (hidden comment: BLM15AX102SN1D)
R33  ValueDisplayed: 10.0k  [0402]  (hidden comment: CRCW040210K0FKED)
R34  ValueDisplayed: 0  [0201M]  (hidden comment: ERJ-1GE0R00C)
R35  ValueDisplayed: 49.9  [0201]  (hidden comment: ERJ-1GEF49R9C)
R36  ValueDisplayed: 49.9  [0201]  (hidden comment: ERJ-1GEF49R9C)
R37  ValueDisplayed: 0  [0201]  (hidden comment: ERJ-1GE0R00C)
R38  ValueDisplayed: 49.9  [0201]  (hidden comment: ERJ-1GEF49R9C)
R39  ValueDisplayed: 0  [0201]  (hidden comment: ERJ-1GE0R00C)
R40  ValueDisplayed: 49.9  [0201]  (hidden comment: ERJ-1GEF49R9C)
R41  ValueDisplayed: 49.9  [0201]  (hidden comment: ERJ-1GEF49R9C)
R42  ValueDisplayed: 49.9  [0201]  (hidden comment: ERJ-1GEF49R9C)
R43  ValueDisplayed: 49.9  [0201]  (hidden comment: ERJ-1GEF49R9C)
R44  ValueDisplayed: 49.9  [0201]  (hidden comment: ERJ-1GEF49R9C)
R45  ValueDisplayed: 49.9  [0201]  (hidden comment: ERJ-1GEF49R9C)
R46  ValueDisplayed: 49.9  [0201]  (hidden comment: ERJ-1GEF49R9C)
R47  ValueDisplayed: 49.9  [0201]  (hidden comment: ERJ-1GEF49R9C)
R48  value 4.7k  [0402]  (hidden comment: CRCW04024K70JNED)
R49  ValueDisplayed: 49.9  [0201]  (hidden comment: ERJ-1GEF49R9C)
R50  ValueDisplayed: 49.9  [0201]  (hidden comment: ERJ-1GEF49R9C)
R51  ValueDisplayed: 49.9  [0201]  (hidden comment: ERJ-1GEF49R9C)
R52  ValueDisplayed: 49.9  [0201]  (hidden comment: ERJ-1GEF49R9C)
R53  value 0  [0402]  (hidden comment: ERJ-2GE0R00X)
R54  ValueDisplayed: 49.9  [0201]  (hidden comment: ERJ-1GEF49R9C)
R55  ValueDisplayed: 49.9  [0201]  (hidden comment: ERJ-1GEF49R9C)
R56  value 0  [0402]  (hidden comment: ERJ-2GE0R00X)
R57  ValueDisplayed: 49.9  [0201]  (hidden comment: ERJ-1GEF49R9C)
R58  ValueDisplayed: 49.9  [0201]  (hidden comment: ERJ-1GEF49R9C)
R59  ValueDisplayed: 49.9  [0201]  (hidden comment: ERJ-1GEF49R9C)
R60  ValueDisplayed: 49.9  [0201]  (hidden comment: ERJ-1GEF49R9C)
R61  ValueDisplayed: 49.9  [0201]  (hidden comment: ERJ-1GEF49R9C)
R62  ValueDisplayed: 49.9  [0201]  (hidden comment: ERJ-1GEF49R9C)
R63  ValueDisplayed: 49.9  [0201]  (hidden comment: ERJ-1GEF49R9C)
R64  value 0  [0402]  (hidden comment: ERJ-2GE0R00X)
R65  ValueDisplayed: 49.9  [0201]  (hidden comment: ERJ-1GEF49R9C)
R66  ValueDisplayed: 49.9  [0201]  (hidden comment: ERJ-1GEF49R9C)
R67  ValueDisplayed: 49.9  [0201]  (hidden comment: ERJ-1GEF49R9C)
R68  ValueDisplayed: 49.9  [0201]  (hidden comment: ERJ-1GEF49R9C)
U1  DS90UB921TRHSRQ1  [RHS0048A]
X1  FXO-HC736R-96  Frequency: 96 MHz  [FOX_FXO-HC73]

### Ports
CMF, DE, DIN0/R0, DIN1/R1, DIN2/R2, DIN3/R3, DIN4/R4, DIN5/R5, DIN6/R6, DIN7/R7, DIN8/G0, DIN9/G1, DIN10/G2, DIN11/G3, DIN12/G4, DIN13/G5, DIN14/G6, DIN15/G7, DIN16/B0, DIN17/B1, DIN18/B2, DIN19/B3, DIN20/B4, DIN21/B5, DIN22/B6, DIN23/B7, DOUT0_N, DOUT0_P, FSEL, HS, I2S_CLK, I2S_DA, I2S_WC, IDx, INTB, MODE_SEL, PCLK, PDB, REM_INTB, SCL, SDA, VS

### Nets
CAPHS_12: U1.17(CAPHS12)
CAPL12: U1.7(CAPL12)
CAPP_12: U1.14(CAPP12)
GND: C4.2 C5.2 J6.2 R35.1 R36.2 R38.2 R40.2 R41.2 R42.2 R43.2 R44.2 R45.2 R46.2 R47.2 R49.2 R50.2 R51.2 R52.2 R54.2 R55.2 R56.2 R57.2 R58.2 R59.2 R60.2 R61.2 R62.2 R63.2 R65.2 R66.2 R67.2 R68.2 U1.49(PAD) X1.2(GND)
VDD33: J4.1
VDD33_C: U1.22(VDD33)
VDDIO: J4.3
VDDIO_C: R48.2 U1.30(VDDIO)
CMF: U1.23(CMF) ; port CMF
DE: R68.1 U1.5(DE) ; port DE
DIN0/R0: R35.2 U1.25(DIN0/R0/GPIO0) ; port DIN0/R0
DIN1/R1: R36.1 U1.26(DIN1/R1/GPIO1) ; port DIN1/R1
DIN2/R2: R38.1 U1.27(DIN2/R2) ; port DIN2/R2
DIN3/R3: R40.1 U1.28(DIN3/R3) ; port DIN3/R3
DIN4/R4: R41.1 U1.29(DIN4/R4) ; port DIN4/R4
DIN5/R5: R42.1 U1.32(DIN5/R5) ; port DIN5/R5
DIN6/R6: R43.1 U1.33(DIN6/R6) ; port DIN6/R6
DIN7/R7: R44.1 U1.34(DIN7/R7) ; port DIN7/R7
DIN8/G0: R45.1 U1.35(DIN8/G0/GPIO2) ; port DIN8/G0
DIN9/G1: R46.1 U1.36(DIN9/G1/GPIO3) ; port DIN9/G1
DIN10/G2: R47.1 U1.37(G2/DIN10) ; port DIN10/G2
DIN11/G3: R49.1 U1.38(G3/DIN11) ; port DIN11/G3
DIN12/G4: R50.1 U1.39(G4/DIN12) ; port DIN12/G4
DIN13/G5: R51.1 U1.40(G5/DIN13) ; port DIN13/G5
DIN14/G6: R52.1 U1.41(G6/DIN14) ; port DIN14/G6
DIN15/G7: R54.1 U1.42(G7/DIN15) ; port DIN15/G7
DIN16/B0: R55.1 U1.43(GPO_REG4/B0/DIN16) ; port DIN16/B0
DIN17/B1: R57.1 U1.44(I2S_DB/GPO_REG5/B1/DIN17) ; port DIN17/B1
DIN18/B2: R58.1 U1.45(B2/DIN18) ; port DIN18/B2
DIN19/B3: R59.1 U1.46(B3/DIN19) ; port DIN19/B3
DIN20/B4: R60.1 U1.47(B4/DIN20) ; port DIN20/B4
DIN21/B5: R61.1 U1.48(B5/DIN21) ; port DIN21/B5
DIN22/B6: R62.1 U1.1(B6/DIN22) ; port DIN22/B6
DIN23/B7: R63.1 U1.2(B7/DIN23) ; port DIN23/B7
DOUT_N: U1.19(DOUT-) ; port DOUT0_N
DOUT_P: U1.20(DOUT+) ; port DOUT0_P
FSEL: U1.15(FSEL) ; port FSEL
HS: R66.1 U1.3(HS) ; port HS
I2S_CLK: U1.13(I2S_CLK) ; port I2S_CLK
I2S_DA: U1.11(GPO_REG6/I2S_DA) ; port I2S_DA
I2S_WC: U1.12(GPO_REG7/I2S_WC) ; port I2S_WC
IDx: U1.6(IDx) ; port IDx
INTB_R: R48.1 R53.1 U1.31(INTB)
MODE_SEL: U1.24(MODE_SEL) ; port MODE_SEL
PCLK: R34.2 R65.1 U1.10(PCLK) ; port PCLK
PDB_R: R64.1 U1.21(PDB)
REM_INTB: U1.16(REM_INTB) ; port REM_INTB
RES1: R56.1 U1.18(RES1)
SCL: R39.2 ; port SCL
SCL_R: R39.1 U1.8(SCL)
SDA: R37.2 ; port SDA
SDA_R: R37.1 U1.9(SDA)
VS: R67.1 U1.4(VS) ; port VS
NetC3_1: R64.2 ; port PDB
NetC4_1: C4.1 J5.1 L1.1 R33.2
NetC5_1: C5.1 J5.2 X1.4(VCC)
NetJ4_2: J4.2 L1.2
NetJ6_1: J6.1 R33.1 X1.1(E/D)
NetJ32_1: R53.2 ; port INTB
NetR34_1: R34.1 X1.3(OUT)

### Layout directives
rule Undefined: (no net found under the mark)
differential pair: DOUT_N, DOUT_P

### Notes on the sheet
- PLACE RESISTORS UNDER BOARD
- (near R63) DNI RESISTORS ABOVE
- (near R68) DNI RESISTORS R212-R215

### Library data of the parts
C4 = GRM21BR71C475KA73L: CAP, CERM, 4.7uF, 16V, +/-10%, X7R, 0805; Manufacturer: MuRata; Polarized: N; CompType: Capacitor; U/M: EA; Cap_F: 0.0000047; Tolerance_%: 10; ESR_Ohm: 0.006; Value1: 0.006 ohm; VDC_V: 16; TaMin_C: -55; TaMax_C: 125; Cap_Case: 0805
C5 = 06031C103JAT2A: CAP, CERM, 0.01uF, 100V, +/-5%, X7R, 0603; Manufacturer: AVX; Polarized: N; CompType: Capacitor; U/M: EA; Cap_F: 0.00000001; Tolerance_%: 5; ESR_Ohm: 0.098; Value1: 0.098 ohm; VDC_V: 100; TaMin_C: -55; TaMax_C: 125
J4 = TSW-103-07-G-S: Header, 100mil, 3x1, Gold, TH; Manufacturer: Samtec; SymbolCreator: a0799628; U/M: EA
J5 J6 = 5-146261-1: as J1 on sheet SV601263A_CONFIG
L1 = BLM15AX102SN1D: Ferrite Bead, 1000 ohm @ 100 MHz, 0.35 A, 0402; Manufacturer: MuRata; Imax_A: 0.35; DCR_ohm: 0.49; Value1: 0.49 ohm; Value2: 0.35A; ZTyp@100MHz_Ohm: 1000
R33 = CRCW040210K0FKED: as R15 on sheet SV601263A_CONFIG
R34 = ERJ-1GE0R00C: RES, 0, 5%, 0.05 W, 0201; Manufacturer: Panasonic; CompType: Resistor; Value: 0; Value_Code: 0000; Tolerance_%: 5; Power_W: 0.05; Value2: 0.05W; VDC_V: 15; TempCo: 600 ppm/C; EIA_Code: E24; U/M: EA
R35 R36 R38 R40-R47 R49-R52 R54 R55 R57-R63 R65-R68 = ERJ-1GEF49R9C: RES, 49.9, 1%, 0.05 W, 0201; Manufacturer: Panasonic; CompType: Resistor; Value: 49.9; Value_Code: 49R9; Tolerance_%: 1; Power_W: 0.05; Value2: 0.05W; VDC_V: 25; TempCo: 200 ppm/C; EIA_Code: E96; U/M: EA
R37 R39 = ERJ-1GE0R00C: as R121 on sheet SV601263A_CONNECTORS
R48 = CRCW04024K70JNED: as R115 on sheet SV601263A_CONNECTORS
R53 R56 R64 = ERJ-2GE0R00X: as R1 on sheet SV601263A_CONFIG
U1 = DS90UB921TRHSRQ1: 5 - 96 MHz 24-bit Color FPD-Link III Serializer with Bidirectional Control Channel, RHS0048A; Alternate PartNumber: DS90UB921TRHSTQ1; Manufacturer: Texas Instruments; SymbolCreator: Altium; CompType: IC; U/M: EA
X1 = FXO-HC736R-96: OSC, 96 MHz, 3.3 Vdc, SMD; Manufacturer: Fox Electronics; SymbolCreator: a0411947; CompType: Oscillator; U/M: EA; TaMin_C: -40; TaMax_C: 85; Frequency Stability: ±25ppm

## Sheet SV601263A_LED.SchDoc
size 431 x 279 mm; Date: Not shown in title block; ApprovedBy: Not shown in title block; CheckedBy: Not shown in title block; Author: Not shown in title block; CompanyName: Not shown in title block; Engineer: Not shown in title block; Organization: Not shown in title block; Address1: Not shown in title block; Address2: Not shown in title block; Address3: Not shown in title block; Address4: Not shown in title block; DocumentNumber: 8; Revision: Use project parameter SCH_Rev; SheetNumber: 8; SheetTotal: 8; PageSetup: Record=PageOptions¦CenterHorizontal=True¦CenterVertical=True¦PrintScale=1.00¦XCorrection=1.00¦YCorrection=1.00¦PrintKind=0¦BorderSize=5000000¦LeftOffset=0¦BottomOffset=0¦Orientation=2¦PaperLength=1000¦PaperWidth=1000¦Scale=100¦PaperSource=15¦PrintQuality=600¦MediaType=1¦DitherType=10¦PaperKind=Letter¦PrintScaleMode=1
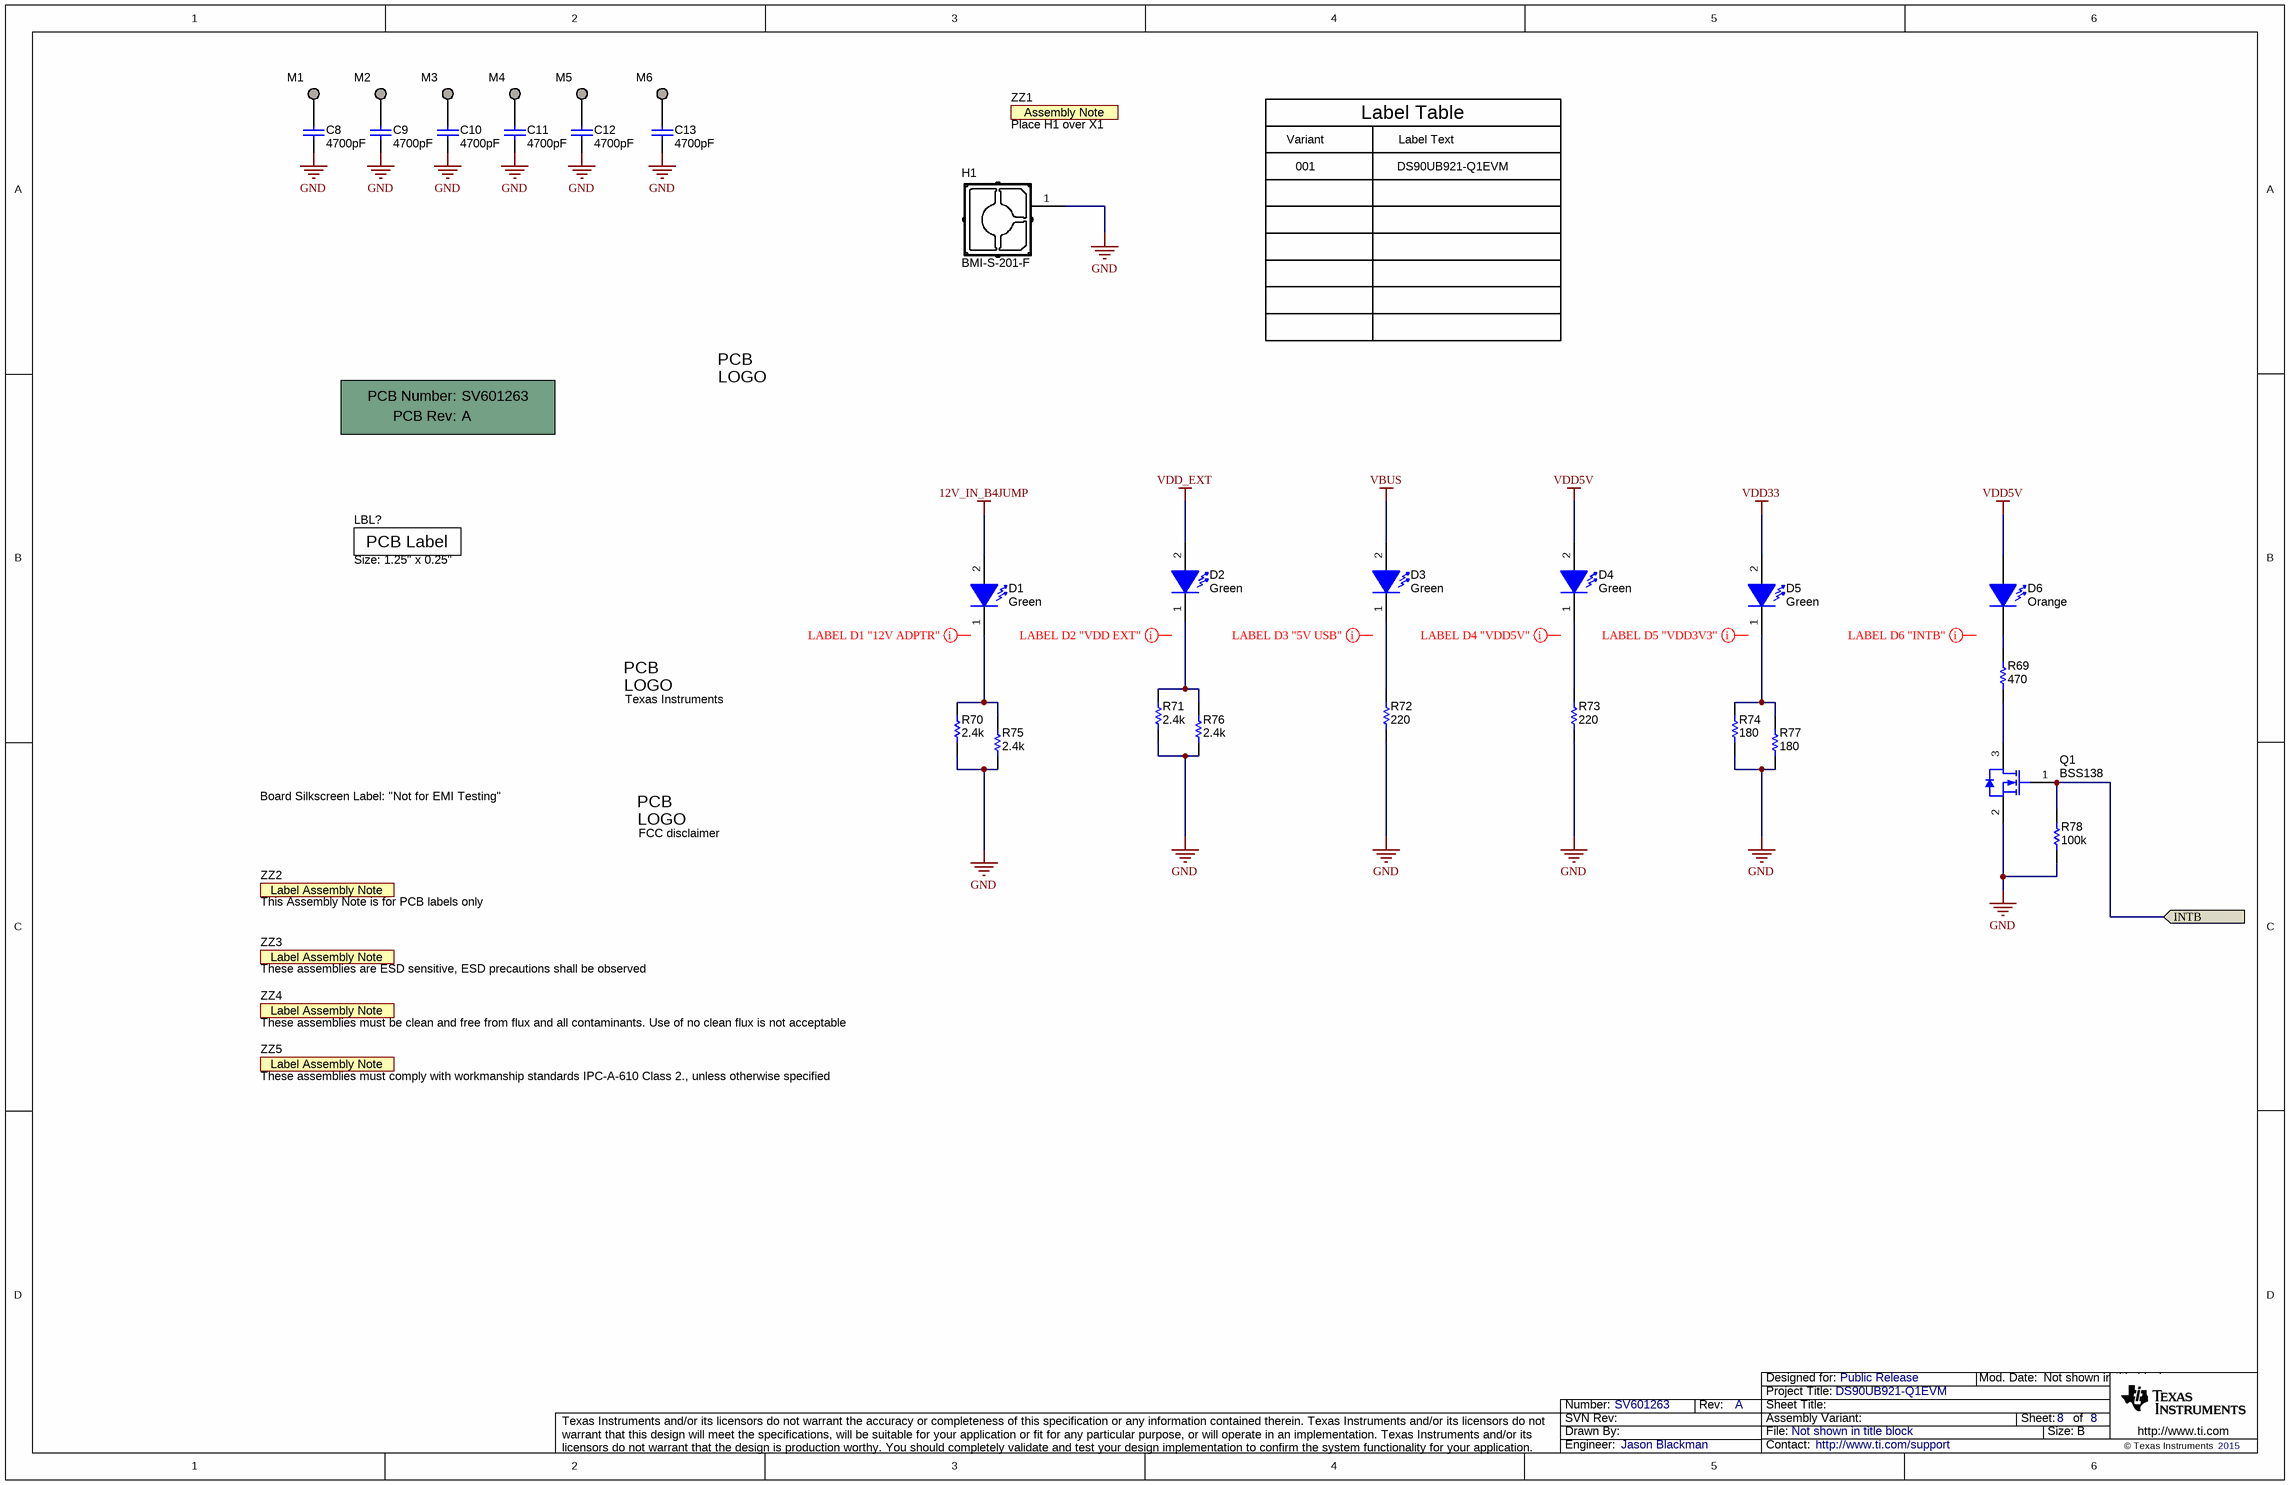
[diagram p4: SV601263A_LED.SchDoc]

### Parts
!PCB1  Printed Circuit Board  (value not drawn)  (mechanical)
C8  ValueDisplayed: 4700pF  [0805_HV]  (hidden comment: 08051C472KAT2A)
C9  ValueDisplayed: 4700pF  [0805_HV]  (hidden comment: 08051C472KAT2A)
C10  ValueDisplayed: 4700pF  [0805_HV]  (hidden comment: 08051C472KAT2A)
C11  ValueDisplayed: 4700pF  [0805_HV]  (hidden comment: 08051C472KAT2A)
C12  ValueDisplayed: 4700pF  [0805_HV]  (hidden comment: 08051C472KAT2A)
C13  ValueDisplayed: 4700pF  [0805_HV]  (hidden comment: 08051C472KAT2A)
D1  value Green  [WL-SMCW_GREEN]  (hidden comment: 150060VS75000)
D2  value Green  [WL-SMCW_GREEN]  (hidden comment: 150060VS75000)
D3  value Green  [WL-SMCW_GREEN]  (hidden comment: 150060VS75000)
D4  value Green  [WL-SMCW_GREEN]  (hidden comment: 150060VS75000)
D5  value Green  [WL-SMCW_GREEN]  (hidden comment: 150060VS75000)
D6  value Orange  [LED_LTST-C190]  (hidden comment: LTST-C190KFKT)
H1  BMI-S-201-F  [Laird_BMI-S-201-F]
LBL?  Size: 1.25" x 0.25"  [Label_1250x250]
Logo1  Texas Instruments  [TI_Stacked_Overlay_Small]  (no BOM)
Logo2  FCC disclaimer  [FCC_disclaimer]  (no BOM)
Logo?  Pb-Free Symbol  [Pb-Free_Overlay_Medium]  (value not drawn)  (no BOM)
M1  TESTPOINT  [TESTPOINT]  (value not drawn)  (no BOM)
M2  TESTPOINT  [TESTPOINT]  (value not drawn)  (no BOM)
M3  TESTPOINT  [TESTPOINT]  (value not drawn)  (no BOM)
M4  TESTPOINT  [TESTPOINT]  (value not drawn)  (no BOM)
M5  TESTPOINT  [TESTPOINT]  (value not drawn)  (no BOM)
M6  TESTPOINT  [TESTPOINT]  (value not drawn)  (no BOM)
Q1  BSS138  [SOT-23]
R69  value 470  [0402]  (hidden comment: CRCW0402470RJNED)
R70  ValueDisplayed: 2.4k  [0402]  (hidden comment: CRCW04022K40JNED)
R71  ValueDisplayed: 2.4k  [0402]  (hidden comment: CRCW04022K40JNED)
R72  ValueDisplayed: 220  [0402]  (hidden comment: CRCW0402220RJNED)
R73  ValueDisplayed: 220  [0402]  (hidden comment: CRCW0402220RJNED)
R74  ValueDisplayed: 180  [0402]  (hidden comment: CRCW0402180RJNED)
R75  ValueDisplayed: 2.4k  [0402]  (hidden comment: CRCW04022K40JNED)
R76  ValueDisplayed: 2.4k  [0402]  (hidden comment: CRCW04022K40JNED)
R77  ValueDisplayed: 180  [0402]  (hidden comment: CRCW0402180RJNED)
R78  value 100k  [0402]  (hidden comment: CRCW0402100KJNED)
ZZ1  Place H1 over X1  [AssemblyNote]  (no BOM)
ZZ2  This Assembly Note is for PCB labels only  [AssemblyNoteLabel]  (no BOM)
ZZ3  These assemblies are ESD sensitive, ESD precautions shall be observed  [AssemblyNoteLabel]  (no BOM)
ZZ4  These assemblies must be clean and free from flux and all contaminants. Use of no clean flux is not acceptable  [AssemblyNoteLabel]  (no BOM)
ZZ5  These assemblies must comply with workmanship standards IPC-A-610 Class 2., unless otherwise specified  [AssemblyNoteLabel]  (no BOM)

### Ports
INTB

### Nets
12V_IN_B4JUMP: D1.2(A)
GND: C8.2 C9.2 C10.2 C11.2 C12.2 C13.2 H1.1 Q1.2(S) R70.1 R71.1 R72.1 R73.1 R74.1 R75.1 R76.1 R77.1 R78.1
VBUS: D3.2(A)
VDD5V: D4.2(A) D6.1(A)
VDD33: D5.2(A)
VDD_EXT: D2.2(A)
NetC8_1: C8.1 M1.1
NetC9_1: C9.1 M2.1
NetC10_1: C10.1 M3.1
NetC11_1: C11.1 M4.1
NetC12_1: C12.1 M5.1
NetC13_1: C13.1 M6.1
NetD1_1: D1.1(K) R70.2 R75.2
NetD2_1: D2.1(K) R71.2 R76.2
NetD3_1: D3.1(K) R72.2
NetD4_1: D4.1(K) R73.2
NetD5_1: D5.1(K) R74.2 R77.2
NetD6_2: D6.2(K) R69.2
NetJ32_1: Q1.1(G) R78.2 ; port INTB
NetQ1_3: Q1.3(D) R69.1

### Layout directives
rule Undefined: (no net found under the mark)

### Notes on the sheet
- Variant
- 001
- Label Table
- Label Text
- DS90UB921-Q1EVM
- Board Silkscreen Label: "Not for EMI Testing"

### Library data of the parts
!PCB1 = PCB: Manufacturer: Any; PartNumber: SV601263; SymbolCreator: a0412235
C8-C13 = 08051C472KAT2A: CAP, CERM, 4700 pF, 100 V, +/- 10%, X7R, 0805; Manufacturer: AVX; Polarized: N; CompType: Capacitor; Value: 4700pF; U/M: EA; Cap_F: 0.0000000047; Tolerance_%: 10; ESR_ohm: 0.119; Value1: 0.119 ohm; VDC_V: 100; Value2: 100V; TaMin_C: -55; TaMax_C: 125; Cap_Case: 0805
D1-D5 = 150060VS75000: LED, Green, SMD; Manufacturer: Wurth Elektronik eiSos; Type: AlInGaP; Vf_V: 2; Value2: 2V; Io_A: 0.02; Value1: W; U/M: EA
D6 = LTST-C190KFKT: LED, Orange, SMD; Manufacturer: Lite-On; Type: AlInGaP; Vf_V: 2; Value2: 2V; Io_A: 0.02; Power_TotalModule: 0.075; Value1: 0.075W; U/M: EA
H1 = BMI-S-201-F: EMI SHIELD, 13.66 x 12.70 mm, SMT; Manufacturer: Laird-Signal Integrity Products; SymbolCreator: Altium
LBL? = THT-13-457-10: Thermal Transfer Printable Labels, 1.250" W x 0.250" H - 10,000 per roll; Manufacturer: Brady; SymbolCreator: a0412235; CompType: Label
Logo1 = TI_Logo: Texas Instrument Corporate Signature; SymbolCreator: a0412235
Logo2 = FCC_disclaimer: SymbolCreator: codlsc
Logo? = Pb-Free: SymbolCreator: a0412235
M1-M6 = TESTPOINT: TEST POINT.  No entry in BOM.
Q1 = BSS138: MOSFET, N-CH, 50 V, 0.22 A, SOT-23; Manufacturer: Fairchild Semiconductor; Alternate Manufacturer: None; U/M: EA; ChType: N; Value: 50V; VdsMax_V: 50; Value1: 6 ohm; Rdson45_ohm: 6; Value2: 1.7 nC; QgTyp_nC: 1.7; Vgs_V: 20; IdsMax_A: 0.22
R69 = CRCW0402470RJNED: RES, 470 ohm, 5%, 0.063W, 0402; Manufacturer: Vishay-Dale; CompType: Resistor; Value_Code: 470R; Tolerance_%: 5; Power_W: 0.063; VDC_V: 50; TempCo: 200 ppm/C; EIA_Code: E24; U/M: EA
R70 R71 R75 R76 = CRCW04022K40JNED: RES, 2.4 k, 5%, 0.063 W, 0402; Manufacturer: Vishay-Dale; CompType: Resistor; Value: 2.4k; Res_ohm: 2400; Value_Code: 2k40; Tolerance_%: 5; Power_W: 0.063; Value2: 0.063W; VDC_V: 50; TempCo: 200 ppm/C; EIA_Code: E24; U/M: EA
R72 R73 = CRCW0402220RJNED: RES, 220, 5%, 0.063 W, 0402; Manufacturer: Vishay-Dale; CompType: Resistor; Value: 220; Value_Code: 220R; Tolerance_%: 5; Power_W: 0.063; Value2: 0.063W; VDC_V: 50; TempCo: 200 ppm/C; EIA_Code: E24; U/M: EA
R74 R77 = CRCW0402180RJNED: RES, 180, 5%, 0.063 W, 0402; Manufacturer: Vishay-Dale; CompType: Resistor; Value: 180; Value_Code: 180R; Tolerance_%: 5; Power_W: 0.063; Value2: 0.063W; VDC_V: 50; TempCo: 200 ppm/C; EIA_Code: E24; U/M: EA
R78 = CRCW0402100KJNED: RES, 100k ohm, 5%, 0.063W, 0402; Manufacturer: Vishay-Dale; CompType: Resistor; Res_ohm: 100000; Tolerance_%: 5; Power_W: 0.063; VDC_V: 50; TempCo: 200 ppm/C; EIA_Code: E24; U/M: EA
ZZ1 = AssemblyNote: SymbolCreator: codlsc
ZZ2-ZZ5 = AssemblyNoteLabel: SymbolCreator: a0412235

## Sheet SV601263A_MSP430F5529.SchDoc: USB2ANY
size 558 x 431 mm; Date: 12/14/2010; CompanyName: Texas Instruments; DrawnBy: Downs; Engineer: R. Downs; DocumentNumber: 1; Revision: A; SheetNumber: 2; SheetTotal: 8; Drawn Date: 12/14/2010; Start Date: 2/16/2011; Number: HPA665; Name: Downs; PageSetup: Record=PageOptions¦CenterHorizontal=True¦CenterVertical=True¦PrintScale=0.95¦XCorrection=1.00¦YCorrection=1.00¦PrintKind=1¦BorderSize=5000000¦LeftOffset=0¦BottomOffset=0¦Orientation=2¦PaperLength=1000¦PaperWidth=1000¦Scale=100¦PaperSource=15¦PrintQuality=-3¦MediaType=1¦DitherType=10¦PaperKind=11x17¦PrintScaleMode=1
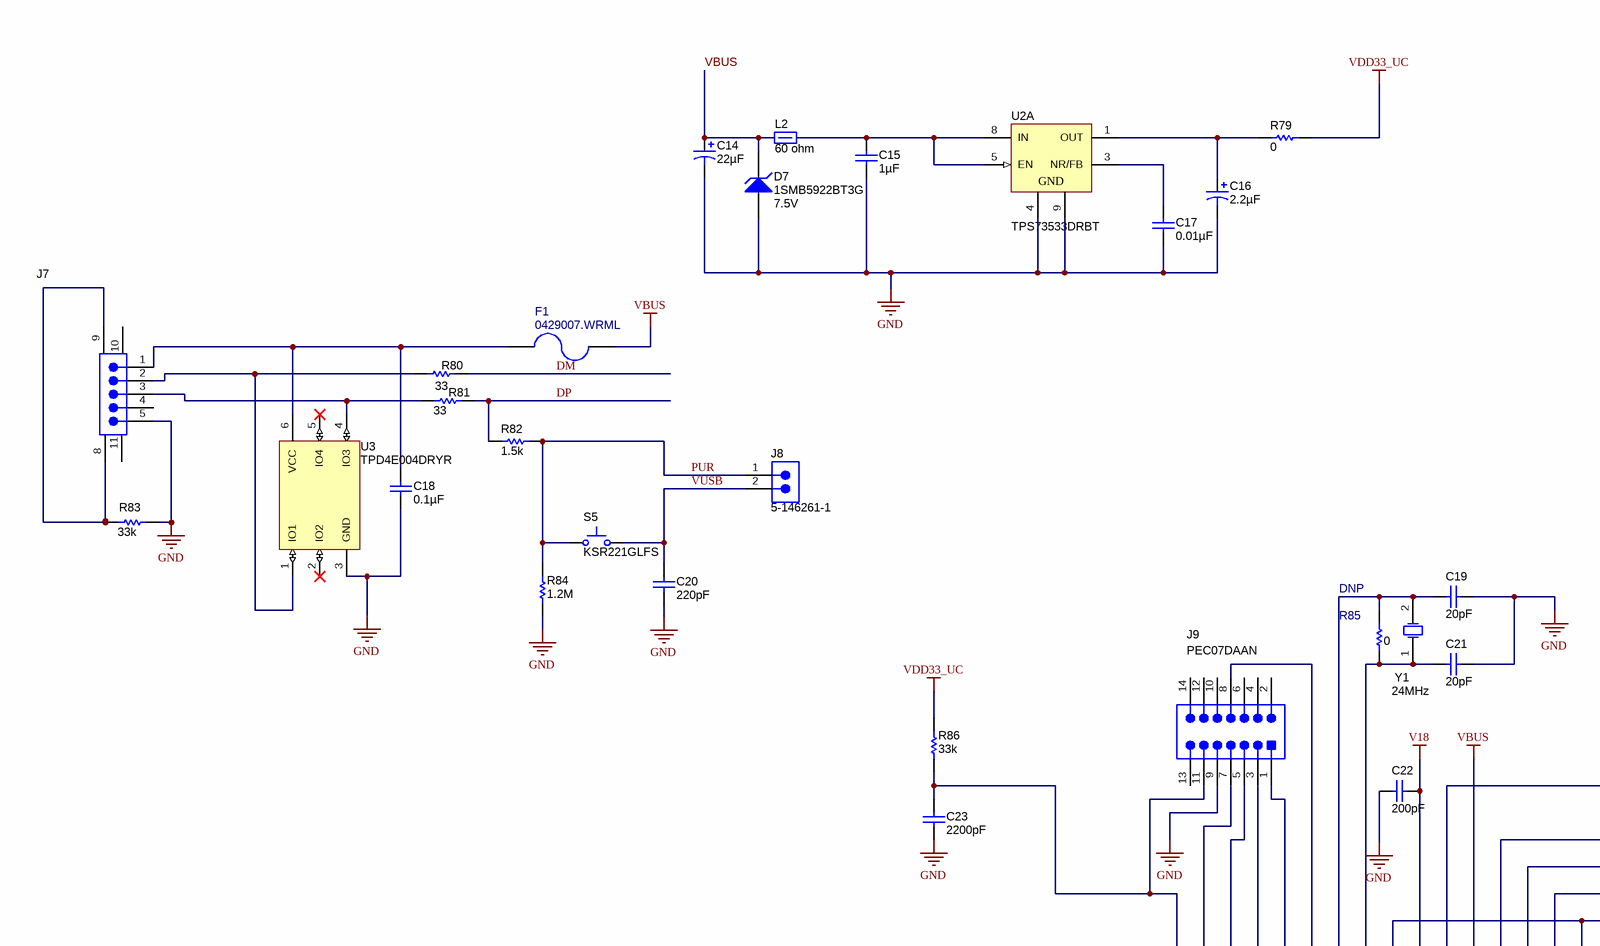
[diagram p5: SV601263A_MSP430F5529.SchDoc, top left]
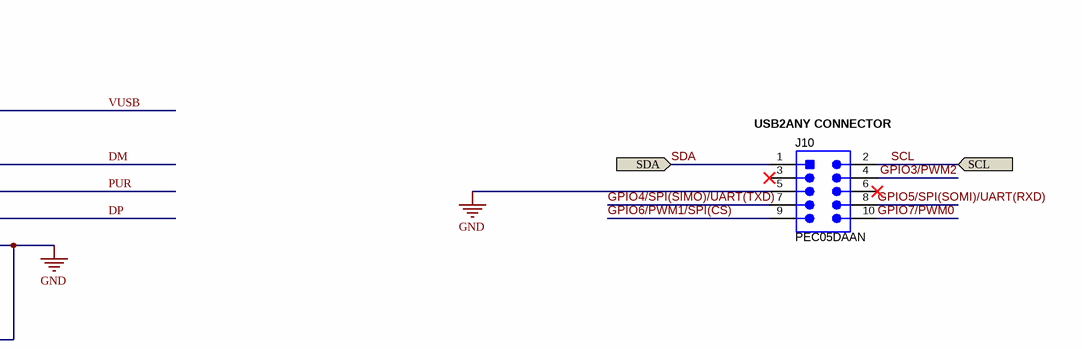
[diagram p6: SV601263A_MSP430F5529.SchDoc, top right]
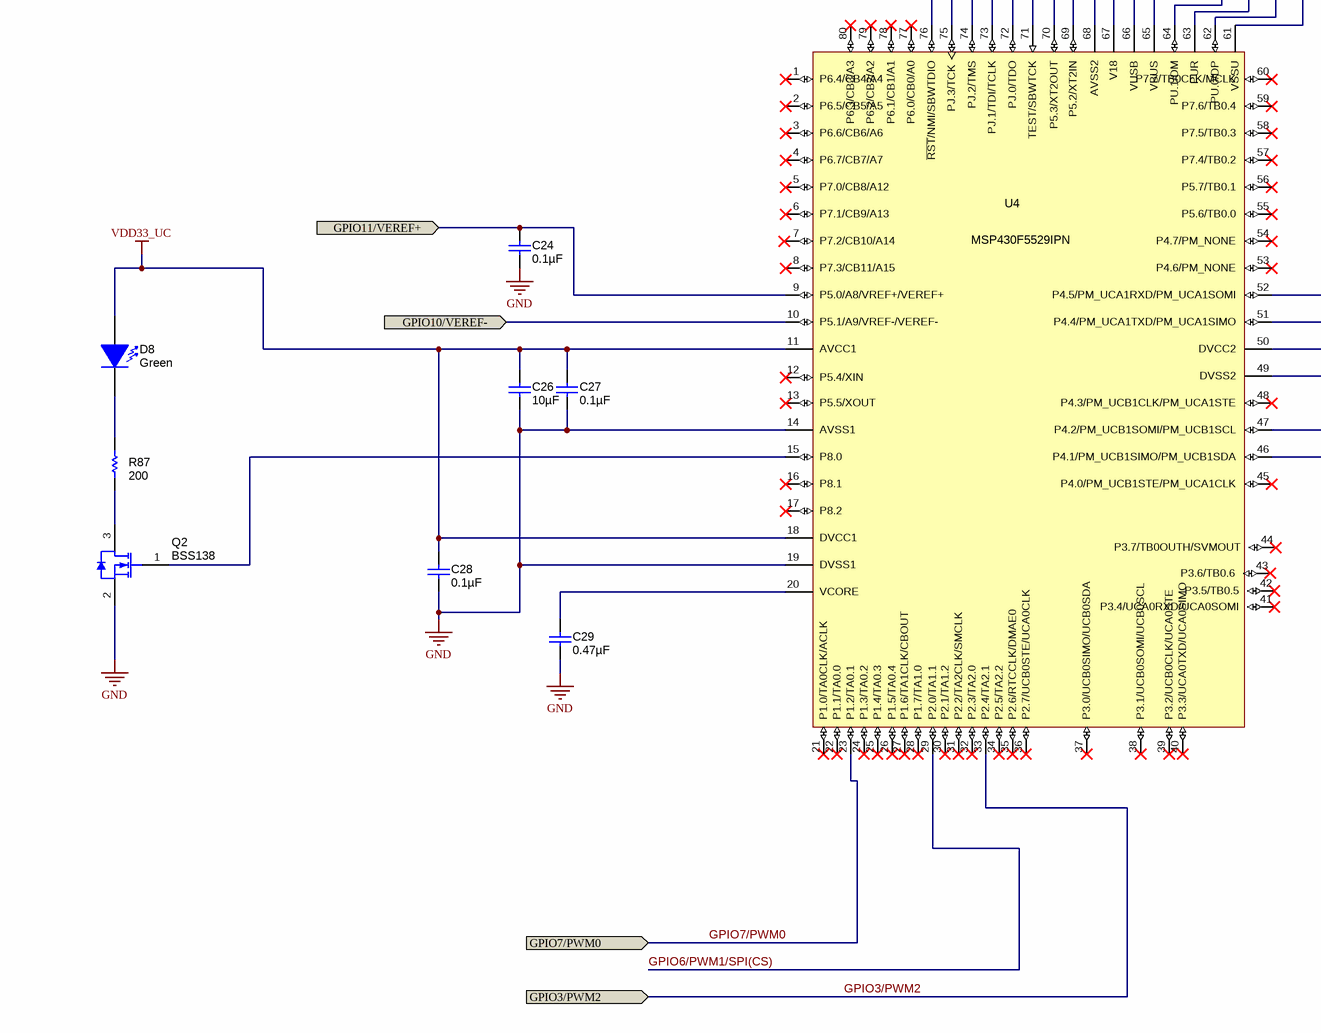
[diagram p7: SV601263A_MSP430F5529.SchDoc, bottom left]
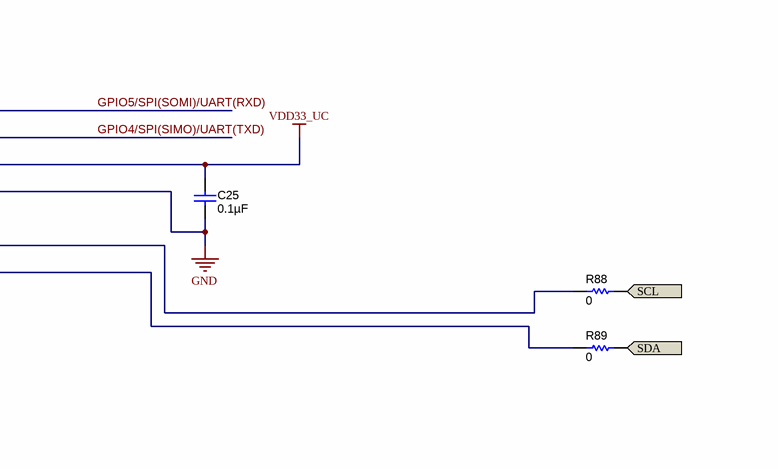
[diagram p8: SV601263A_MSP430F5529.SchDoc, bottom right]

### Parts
C14  ValueDisplayed: 22µF  [7343-31]  (hidden comment: 293D226X0020D2TE3)
C15  ValueDisplayed: 1µF  [0402]  (hidden comment: C1005X5R0J105M050BB)
C16  ValueDisplayed: 2.2µF  [3528-21]  (hidden comment: 293D225X9025B2TE3)
C17  ValueDisplayed: 0.01µF  [0805_HV]  (hidden comment: 08051C103KAT2A)
C18  ValueDisplayed: 0.1µF  [0402]  (hidden comment: GRM155R71C104KA88D)
C19  ValueDisplayed: 20pF  [0603]  (hidden comment: GRM1885C2A200JA01D)
C20  ValueDisplayed: 220pF  [0603]  (hidden comment: 06035A221FAT2A)
C21  ValueDisplayed: 20pF  [0603]  (hidden comment: GRM1885C2A200JA01D)
C22  ValueDisplayed: 200pF  [0402]  (hidden comment: GRM1555C1H201JA01D)
C23  ValueDisplayed: 2200pF  [0603]  (hidden comment: C0603X222K5RACTU)
C24  ValueDisplayed: 0.1µF  [0402]  (hidden comment: GRM155R71C104KA88D)
C25  ValueDisplayed: 0.1µF  [0402]  (hidden comment: GRM155R71C104KA88D)
C26  ValueDisplayed: 10µF  [0805_HV]  (hidden comment: GRM21BR71A106KE51L)
C27  ValueDisplayed: 0.1µF  [0402]  (hidden comment: GRM155R71C104KA88D)
C28  ValueDisplayed: 0.1µF  [0402]  (hidden comment: GRM155R71C104KA88D)
C29  ValueDisplayed: 0.47µF  [0603]  (hidden comment: GRM188R71C474KA88D)
D7  1SMB5922BT3G  value 7.5V  [SMB]
D8  value Green  [LED_LTST-C190]  (hidden comment: LTST-C190GKT)
F1  0429007.WRML  [FUSE_429]
J7  1734035-2  [CONN_USB-Mini-B-1734035-2]  (value not drawn)
J8  5-146261-1  [CONN_5-146261-1]
J9  PEC07DAAN  [CONN_PEC07DAAN]
J10  PEC05DAAN  [CONN_PEC05DAAN]
L2  value 60 ohm  [0603]  (hidden comment: BK1608HS600-T)
Q2  BSS138  [SOT-23]
R79  ValueDisplayed: 0  [0603]  (hidden comment: CRCW06030000Z0EA)
R80  value 33  [0402]  (hidden comment: CRCW040233R0JNED)
R81  value 33  [0402]  (hidden comment: CRCW040233R0JNED)
R82  ValueDisplayed: 1.5k  [0402]  (hidden comment: CRCW04021K50JNED)
R83  value 33k  [0402]  (hidden comment: CRCW040233K0JNED)
R84  ValueDisplayed: 1.2M  [0603]  (hidden comment: CRCW06031M20JNEA)
R85  DNP  ValueDisplayed: 0  [0402]
R86  value 33k  [0402]  (hidden comment: CRCW040233K0JNED)
R87  value 200  [0402]  (hidden comment: CRCW0402200RJNED)
R88  value 0  [0402]  (hidden comment: RC0402JR-070RL)
R89  value 0  [0402]  (hidden comment: RC0402JR-070RL)
S5  KSR221GLFS  [KSR]
U2  TPS73533DRBT  [DRB0008A]  (part A of 2)
U3  TPD4E004DRYR  [DRY0006A]
U4  MSP430F5529IPN  [PN0080A_N]
Y1  Frequency: 24MHz  [XTAL_CSM-7X]  (hidden comment: ECS-240-20-5PX-TR)

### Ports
GPIO3/PWM2 (in), GPIO7/PWM0 (in), GPIO10/VEREF- (in), GPIO11/VEREF+ (in), SCL, SDA

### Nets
GND: C14.2(-) C15.2 C16.2(-) C17.2 C18.1 C19.1 C20.1 C21.1 C22.2 C23.1 C24.2 C25.2 C26.2 C27.1 C28.2 C29.2 D7.2(A) J7.5 J9.9 J10.5 Q2.2(S) R83.1 R84.1 U2.4(GND) U2.9(GND) U3.3(GND) U4.14(AVSS1) U4.19(DVSS1) U4.49(DVSS2) U4.61(VSSU) U4.68(AVSS2)
V18: C22.1 U4.67(V18)
VBUS: C14.1(+) D7.1(K) F1.1 L2.1 U4.65(VBUS)
VDD33_UC: C25.1 C26.1 C27.2 C28.1 D8.1(A) R79.2 R86.1 U4.11(AVCC1) U4.18(DVCC1) U4.50(DVCC2)
DM: R80.1 U4.64(PU.1/DM)
DP: R81.1 R82.2 U4.62(PU.0/DP)
GPIO3/PWM2: J10.4 U4.33(P2.4/TA2.1) ; port GPIO3/PWM2
GPIO4/SPI(SIMO)/UART(TXD): J10.7 U4.51(P4.4/PM_UCA1TXD/PM_UCA1SIMO)
GPIO5/SPI(SOMI)/UART(RXD): J10.8 U4.52(P4.5/PM_UCA1RXD/PM_UCA1SOMI)
GPIO6/PWM1/SPI(CS): J10.9 U4.29(P2.0/TA1.1)
GPIO7/PWM0: J10.10 U4.23(P1.2/TA0.1) ; port GPIO7/PWM0
PUR: J8.1 R82.1 R84.2 S5.1 U4.63(PUR)
SCL: J10.2 R88.1 ; port SCL
SDA: J10.1 R89.2 ; port SDA
VUSB: C20.2 J8.2 S5.2 U4.66(VUSB)
NetC15_1: C15.1 L2.2 U2.5(EN) U2.8(IN)
NetC16_1: C16.1(+) R79.1 U2.1(OUT)
NetC17_1: C17.1 U2.3(NR/FB)
NetC18_2: C18.2 F1.2 J7.1 U3.6(VCC)
NetC19_2: C19.2 R85.2 U4.70(P5.3/XT2OUT) Y1.2(OSC2)
NetC21_2: C21.2 R85.1 U4.69(P5.2/XT2IN) Y1.1(OSC1)
NetC23_2: C23.2 J9.11 R86.2 U4.76(~{RST}/NMI/SBWTDIO)
NetC24_1: C24.1 U4.9(P5.0/A8/VREF+/VEREF+) ; port GPIO11/VEREF+
NetC29_1: C29.1 U4.20(VCORE)
NetD8_2: D8.2(K) R87.2
NetJ7_2: J7.2 R80.2 U3.1(IO1)
NetJ7_3: J7.3 R81.2 U3.4(IO3)
NetJ7_8: J7.8(GND) J7.9(GND) R83.2
NetJ9_1: J9.1 U4.72(PJ.0/TDO)
NetJ9_3: J9.3 U4.73(PJ.1/TDI/TCLK)
NetJ9_5: J9.5 U4.74(PJ.2/TMS)
NetJ9_7: J9.7 U4.75(PJ.3/TCK)
NetJ9_8: J9.8 U4.71(TEST/SBWTCK)
NetQ2_1: Q2.1(G) U4.15(P8.0)
NetQ2_3: Q2.3(D) R87.1
NetR88_2: R88.2 U4.47(P4.2/PM_UCB1SOMI/PM_UCB1SCL)
NetR89_1: R89.1 U4.46(P4.1/PM_UCB1SIMO/PM_UCB1SDA)
NetU4_10: U4.10(P5.1/A9/VREF-/VEREF-) ; port GPIO10/VEREF-

Not connected (* = marked no-connect by the designer): J7 4 10(GND) 11(GND); J9 2 4 6 10 12 13 14; J10 3* 6*; U3 2(IO2)* 5(IO4)*; U4 1(P6.4/CB4/A4)* 2(P6.5/CB5/A5)* 3(P6.6/CB6/A6)* 4(P6.7/CB7/A7)* 5(P7.0/CB8/A12)* 6(P7.1/CB9/A13)* 7(P7.2/CB10/A14) 8(P7.3/CB11/A15)* 12(P5.4/XIN)* 13(P5.5/XOUT)* 16(P8.1)* 17(P8.2)* 21(P1.0/TA0CLK/ACLK)* 22(P1.1/TA0.0)* 24(P1.3/TA0.2)* 25(P1.4/TA0.3)* 26(P1.5/TA0.4)* 27(P1.6/TA1CLK/CBOUT)* 28(P1.7/TA1.0)* 30(P2.1/TA1.2)* 31(P2.2/TA2CLK/SMCLK)* 32(P2.3/TA2.0)* 34(P2.5/TA2.2)* 35(P2.6/RTCCLK/DMAE0)* 36(P2.7/UCB0STE/UCA0CLK)* 37(P3.0/UCB0SIMO/UCB0SDA)* 38(P3.1/UCB0SOMI/UCB0SCL)* 39(P3.2/UCB0CLK/UCA0STE)* 40(P3.3/UCA0TXD/UCA0SIMO)* 41(P3.4/UCA0RXD/UCA0SOMI)* 42(P3.5/TB0.5)* 43(P3.6/TB0.6)* 44(P3.7/TB0OUTH/SVMOUT)* 45(P4.0/PM_UCB1STE/PM_UCA1CLK)* 48(P4.3/PM_UCB1CLK/PM_UCA1STE)* 53(P4.6/PM_NONE)* 54(P4.7/PM_NONE)* 55(P5.6/TB0.0)* 56(P5.7/TB0.1)* 57(P7.4/TB0.2)* 58(P7.5/TB0.3)* 59(P7.6/TB0.4)* 60(P7.7/TB0CLK/MCLK)* 77(P6.0/CB0/A0)* 78(P6.1/CB1/A1)* 79(P6.2/CB2/A2)* 80(P6.3/CB3/A3)*

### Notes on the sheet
- (near J10) USB2ANY CONNECTOR

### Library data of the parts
C14 = 293D226X0020D2TE3: CAP, TA, 22uF, 20V, +/-20%, 0.7 ohm, SMD; Manufacturer: Vishay-Sprague; Polarized: Y; CompType: Capacitor; U/M: EA; Cap_F: 0.000022; Tolerance_%: 20; Value1: 0.7 ohm; ESR_Ohm: 0.7; IRMS_A: 0.46; TaMin_C: -55; TaMax_C: 125; Cap_Case: D
C15 = C1005X5R0J105M050BB: CAP, CERM, 1 µF, 6.3 V, +/- 20%, X5R, 0402; Manufacturer: TDK; Polarized: N; CompType: Capacitor; Value: 1uF; U/M: EA; Cap_F: 0.000001; Tolerance_%: 20; ESR_ohm: 0.0079; Value1: 0.0079 ohm; VDC_V: 6.3; Value2: 6.3V; TaMin_C: -55; TaMax_C: 85; AEC Category: Q200
C16 = 293D225X9025B2TE3: CAP, TA, 2.2uF, 25V, +/-10%, 3.8 ohm, SMD; Manufacturer: Vishay-Sprague; Polarized: Y; CompType: Capacitor; U/M: EA; Cap_F: 0.0000022; Tolerance_%: 10; Value1: 3.8 ohm; VDC_V: 25; ESR_Ohm: 3.8; IRMS_A: 0.15; TaMin_C: -55; TaMax_C: 125; Cap_Case: B
C17 = 08051C103KAT2A: CAP, CERM, 0.01uF, 100V, +/-10%, X7R, 0805; Manufacturer: AVX; Polarized: N; CompType: Capacitor; U/M: EA; Cap_F: 0.00000001; Tolerance_%: 10; ESR_Ohm: 0.078; Value1: 0.078 ohm; VDC_V: 100; TaMin_C: -55; TaMax_C: 125; Cap_Case: 0805
C18 C24 C25 C27 C28 = GRM155R71C104KA88D: as C1 on sheet SV601263A_CONFIG
C19 C21 = GRM1885C2A200JA01D: CAP, CERM, 20 pF, 100 V, +/- 5%, C0G/NP0, 0603; Manufacturer: MuRata; Polarized: N; CompType: Capacitor; Value: 20pF; U/M: EA; Cap_F: 0.00000000002; Tolerance_%: 5; Value1: Unknown; VDC_V: 100; Value2: 100V; TaMin_C: -55; TaMax_C: 125
C20 = 06035A221FAT2A: CAP, CERM, 220 pF, 50 V, +/- 1%, C0G/NP0, 0603; Manufacturer: AVX; Polarized: N; CompType: Capacitor; Value: 220pF; U/M: EA; Cap_F: 0.00000000022; Tolerance_%: 1; ESR_ohm: 0.083; Value1: 0.083 ohm; VDC_V: 50; Value2: 50V; TaMin_C: -55; TaMax_C: 125
C22 = GRM1555C1H201JA01D: CAP, CERM, 200 pF, 50 V, +/- 5%, C0G/NP0, 0402; Manufacturer: MuRata; Polarized: N; CompType: Capacitor; Value: 200pF; U/M: EA; Cap_F: 0.0000000002; Tolerance_%: 5; Value1: Unknown; VDC_V: 50; Value2: 50V; TaMin_C: -55; TaMax_C: 125; AEC Category: Q200
C23 = C0603X222K5RACTU: CAP, CERM, 2200 pF, 50 V, +/- 10%, X7R, 0603; Manufacturer: Kemet; Polarized: N; CompType: Capacitor; Value: 2200pF; U/M: EA; Cap_F: 0.0000000022; Tolerance_%: 10; Value1: Unknown; VDC_V: 50; Value2: 50V; TaMin_C: -55; TaMax_C: 125
C26 = GRM21BR71A106KE51L: as C3 on sheet SV601263A_CONFIG
C29 = GRM188R71C474KA88D: CAP, CERM, 0.47uF, 16V, +/-10%, X7R, 0603; Manufacturer: MuRata; Polarized: N; CompType: Capacitor; U/M: EA; Cap_F: 0.00000047; Tolerance_%: 10; Value1: Unknown; VDC_V: 16; TaMin_C: -55; TaMax_C: 125
D7 = 1SMB5922BT3G: Diode, Zener, 7.5V, 550mW, SMB; Manufacturer: ON Semiconductor; SymbolCreator: a0412235; U/M: EA; Power_W: 0.55; Vz_V: 7.5; Value1: 0.55W; RJA_CperW: 226
D8 = LTST-C190GKT: LED, Green, SMD; Manufacturer: Lite-On; Vf_V: 2.1; Value2: 2.1V; Io_A: 0.02; Power_TotalModule: 0.1; Value1: 0.1W; U/M: EA
F1 = 0429007.WRML: Fuse, 7 A, 24 V, SMD; Manufacturer: Littelfuse; U/M: EA; VDC_V: 24; Interrupt_AC: 35; Irating_A: 7; Rtyp_Ohm: 0.00925; MeltingTyp: 3.6
J7 = 1734035-2: Connector, Receptacle, Mini-USB Type B, R/A, Top Mount SMT; Manufacturer: TE Connectivity; SymbolCreator: A0412235; U/M: EA
J8 = 5-146261-1: as J1 on sheet SV601263A_CONFIG
J9 = PEC07DAAN: Header, 100mil, 7x2, Tin, TH; Manufacturer: Sullins Connector Solutions; SymbolCreator: a0412235; U/M: EA
J10 = PEC05DAAN: Header, 100mil, 5x2, Tin, TH; Manufacturer: Sullins Connector Solutions; SymbolCreator: a0412235; U/M: EA
L2 = BK1608HS600-T: Ferrite Bead, 60 ohm @ 100MHz, 0.8A, 0603; Manufacturer: Taiyo Yuden; Imax_A: 0.8; DCR_ohm: 0.1; Value1: 0.1 ohm; ZTyp@100MHz_Ohm: 60
Q2 = BSS138: as Q1 on sheet SV601263A_LED
R79 = CRCW06030000Z0EA: RES, 0, 5%, 0.1 W, 0603; Manufacturer: Vishay-Dale; CompType: Resistor; Value: 0; Value_Code: 0000; Tolerance_%: 5; Power_W: 0.1; Value2: 0.1W; VDC_V: 75; TempCo: 200 ppm/C; EIA_Code: E24; U/M: EA
R80 R81 = CRCW040233R0JNED: RES, 33 ohm, 5%, 0.063W, 0402; Manufacturer: Vishay-Dale; CompType: Resistor; Value_Code: 33R0; Tolerance_%: 5; Power_W: 0.063; VDC_V: 50; TempCo: 200 ppm/C; EIA_Code: E24; U/M: EA
R82 = CRCW04021K50JNED: RES, 1.5 k, 5%, 0.063 W, 0402; Manufacturer: Vishay-Dale; CompType: Resistor; Value: 1.5k; Res_ohm: 1500; Value_Code: 1k50; Tolerance_%: 5; Power_W: 0.063; Value2: 0.063W; VDC_V: 50; TempCo: 200 ppm/C; EIA_Code: E24; U/M: EA
R83 R86 = CRCW040233K0JNED: RES, 33k ohm, 5%, 0.063W, 0402; Manufacturer: Vishay-Dale; CompType: Resistor; Res_ohm: 33000; Value_Code: 33k0; Tolerance_%: 5; Power_W: 0.063; VDC_V: 50; TempCo: 200 ppm/C; EIA_Code: E24; U/M: EA
R84 = CRCW06031M20JNEA: RES, 1.2 M, 5%, 0.1 W, 0603; Manufacturer: Vishay-Dale; CompType: Resistor; Value: 1.2Meg; Res_ohm: 1200000; Value_Code: 1M20; Tolerance_%: 5; Power_W: 0.1; Value2: 0.1W; VDC_V: 75; TempCo: 200 ppm/C; EIA_Code: E24; U/M: EA
R85 = CRCW04020000Z0ED: RES, 0, 5%, 0.063 W, 0402; Manufacturer: Vishay-Dale; CompType: Resistor; Value: 0; Value_Code: 0000; Tolerance_%: 5; Power_W: 0.063; Value2: 0.063W; VDC_V: 50; TempCo: 200 ppm/C; EIA_Code: E24; U/M: EA
R87 = CRCW0402200RJNED: RES, 200 ohm, 5%, 0.063W, 0402; Manufacturer: Vishay-Dale; CompType: Resistor; Value_Code: 200R; Tolerance_%: 5; Power_W: 0.063; VDC_V: 50; TempCo: 200 ppm/C; EIA_Code: E24; U/M: EA
R88 R89 = RC0402JR-070RL: RES, 0, 5%, 0.063 W, 0402; Manufacturer: Yageo America; CompType: Resistor; Value_Code: 0000; Tolerance_%: 5; Power_W: 0.063; Value2: 0.063W; VDC_V: 50; TempCo: 200 ppm/C; EIA_Code: E24; U/M: EA
S5 = KSR221GLFS: as S3 on sheet SV601263A_CONFIG
U2 = TPS73533DRBT: Single Output High PSRR LDO, 500 mA, Fixed 3.3 V Output, 2.7 to 6.5 V Input, with Low IQ, 8-pin SON (DRB), -40 to 125 degC, Green (RoHS & no Sb/Br); Manufacturer: Texas Instruments; Alternate Manufacturer: None; Alternate PartNumber: Equivalent; Accuracy(%): 2; Fixed Output Options(V): 3.3; Iout(Max)(A): 0.5; Iq(Typ)(mA): 0.04; SubFamily: Single Channel LDO; Vdo(Typ)(mV): 280; Vin(Max)(V): 6.5; Vin(Min)(V): 2.7
U3 = TPD4E004DRYR: 4-CHANNEL ESD-PROTECTION ARRAY FOR HIGH-SPEED DATA INTERFACES, DRY006A; Manufacturer: Texas Instruments; SymbolCreator: a0411947; CompType: IC; U/M: EA
U4 = MSP430F5529IPN: Mixed Signal MicroController, PN0080A; Manufacturer: Texas Instruments; ADC: 12-bit SAR; ADC Channels: 16; Brown Out Reset: Yes; DMA: 3; Eco-Plan: Green (RoHS & no Sb/Br); Flash(KB): 128; Frequency(MHz): 25; GPIO: 63; Multiplier: 32x32; SRAM(B): 8192; SubFamily: 5 Series; Timers - 16-bit: 4; USB: 1; USCI_A (UART/LIN/IrDA/SPI): 2; SymbolCreator: Altium/a0412235; CompType: IC; U/M: EA
Y1 = ECS-240-20-5PX-TR: Crystal, 24.000MHz, 20pF, SMD; Manufacturer: ECS Inc.; SymbolCreator: a0412235; U/M: EA; TaMin_C: -10; TaMax_C: 70; Frequency Stability: ±50ppm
